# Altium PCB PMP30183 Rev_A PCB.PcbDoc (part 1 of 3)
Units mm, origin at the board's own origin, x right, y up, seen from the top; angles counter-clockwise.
Board outline 88.14 x 173.35 mm, 4 copper layers (Top Layer, Signal Layer 1, Signal Layer 2, Bottom Layer), stack 2.028 mm thick; 250 components, 133 nets, 589 pads, 226 vias.
Unrouted connection lines stored in the file: 1.
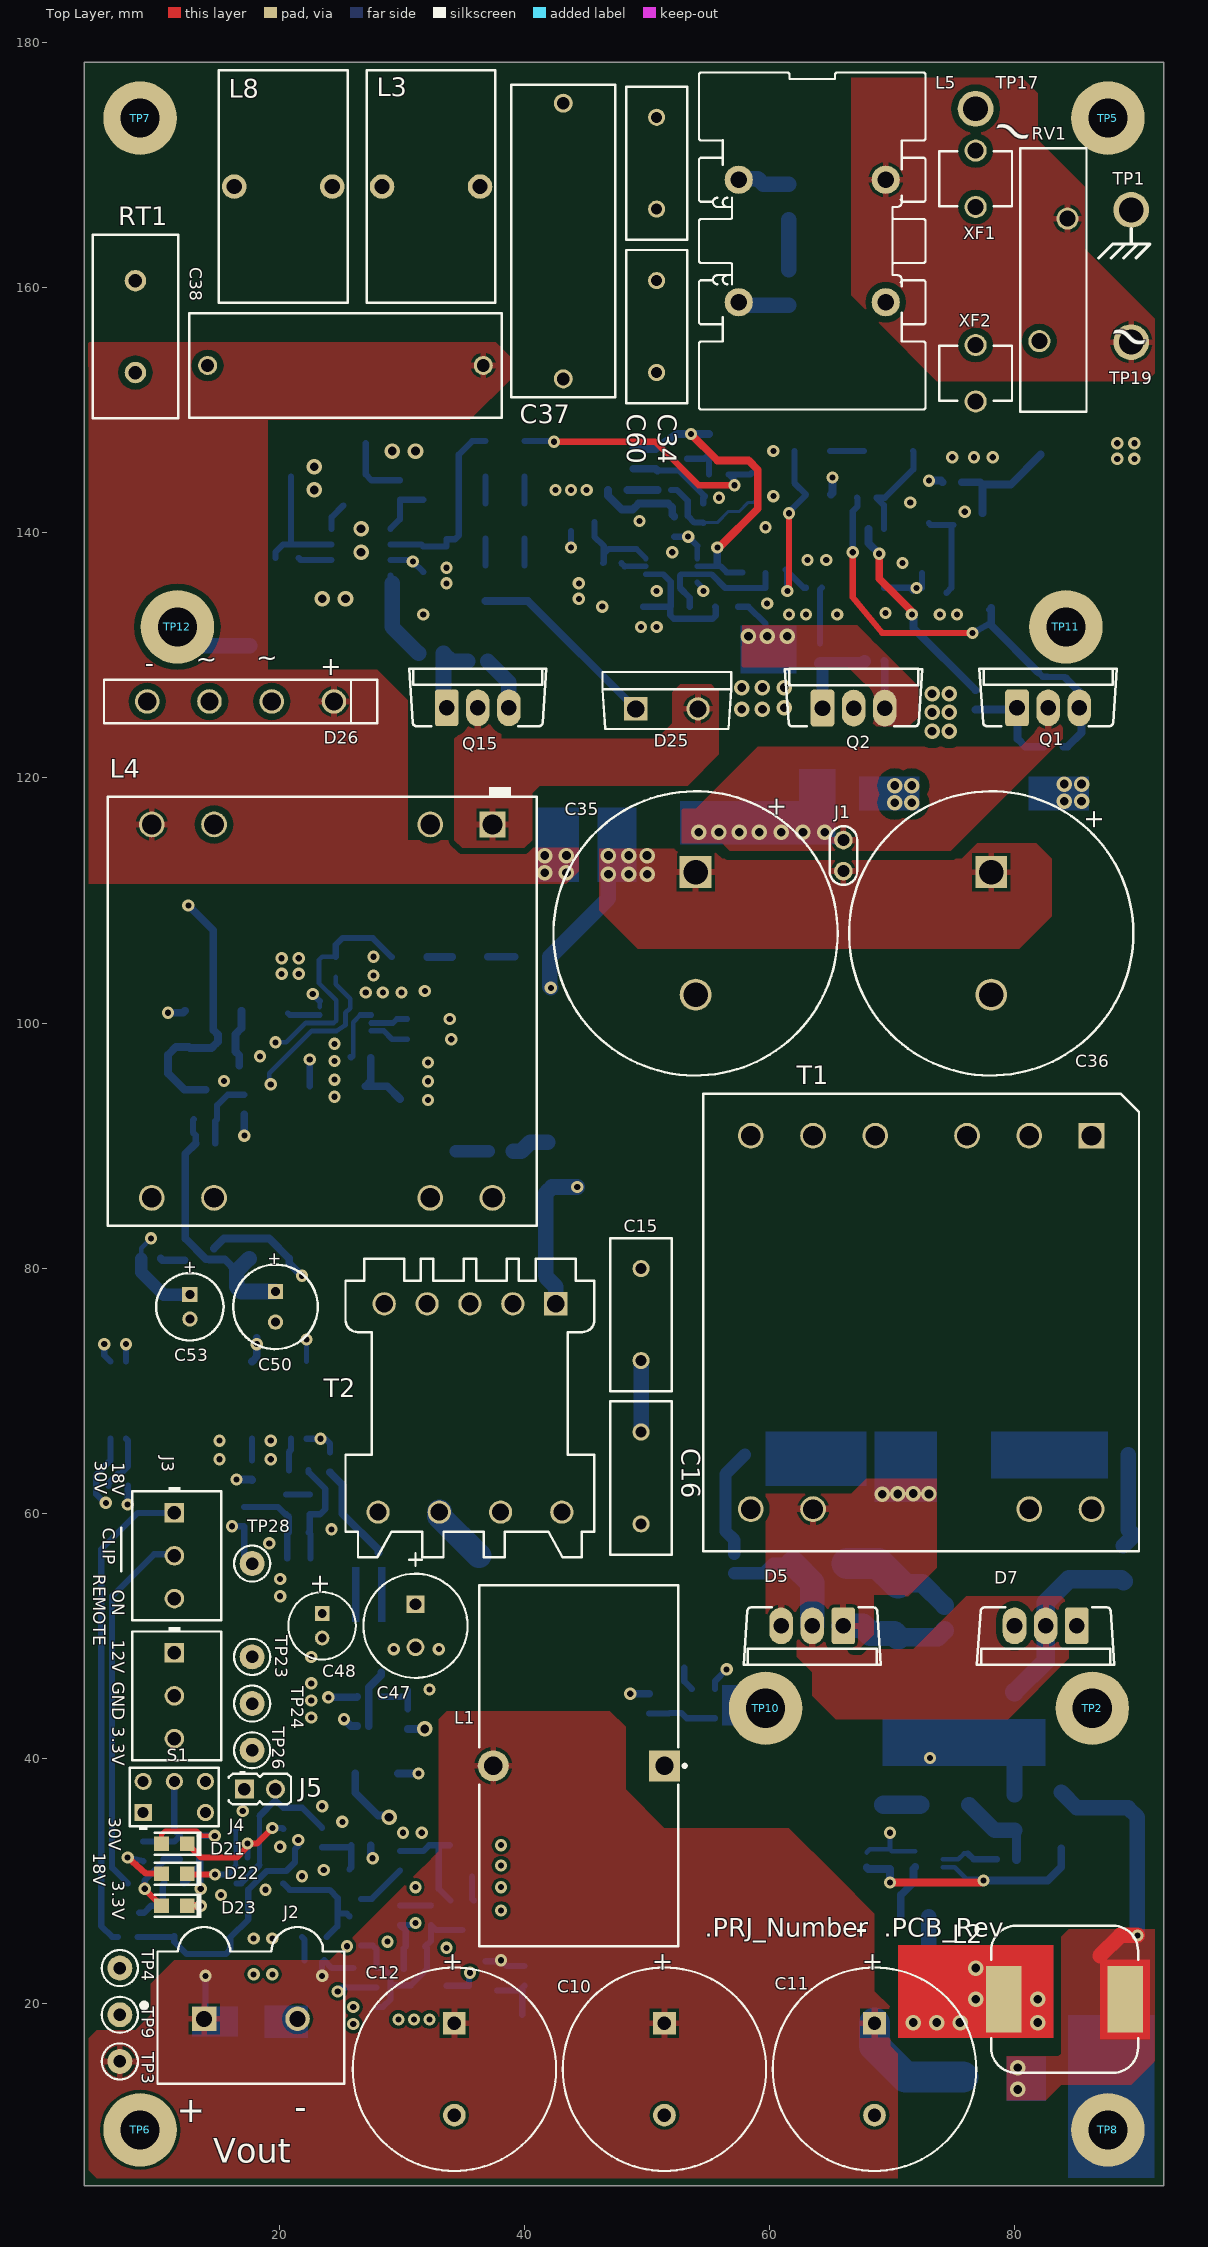
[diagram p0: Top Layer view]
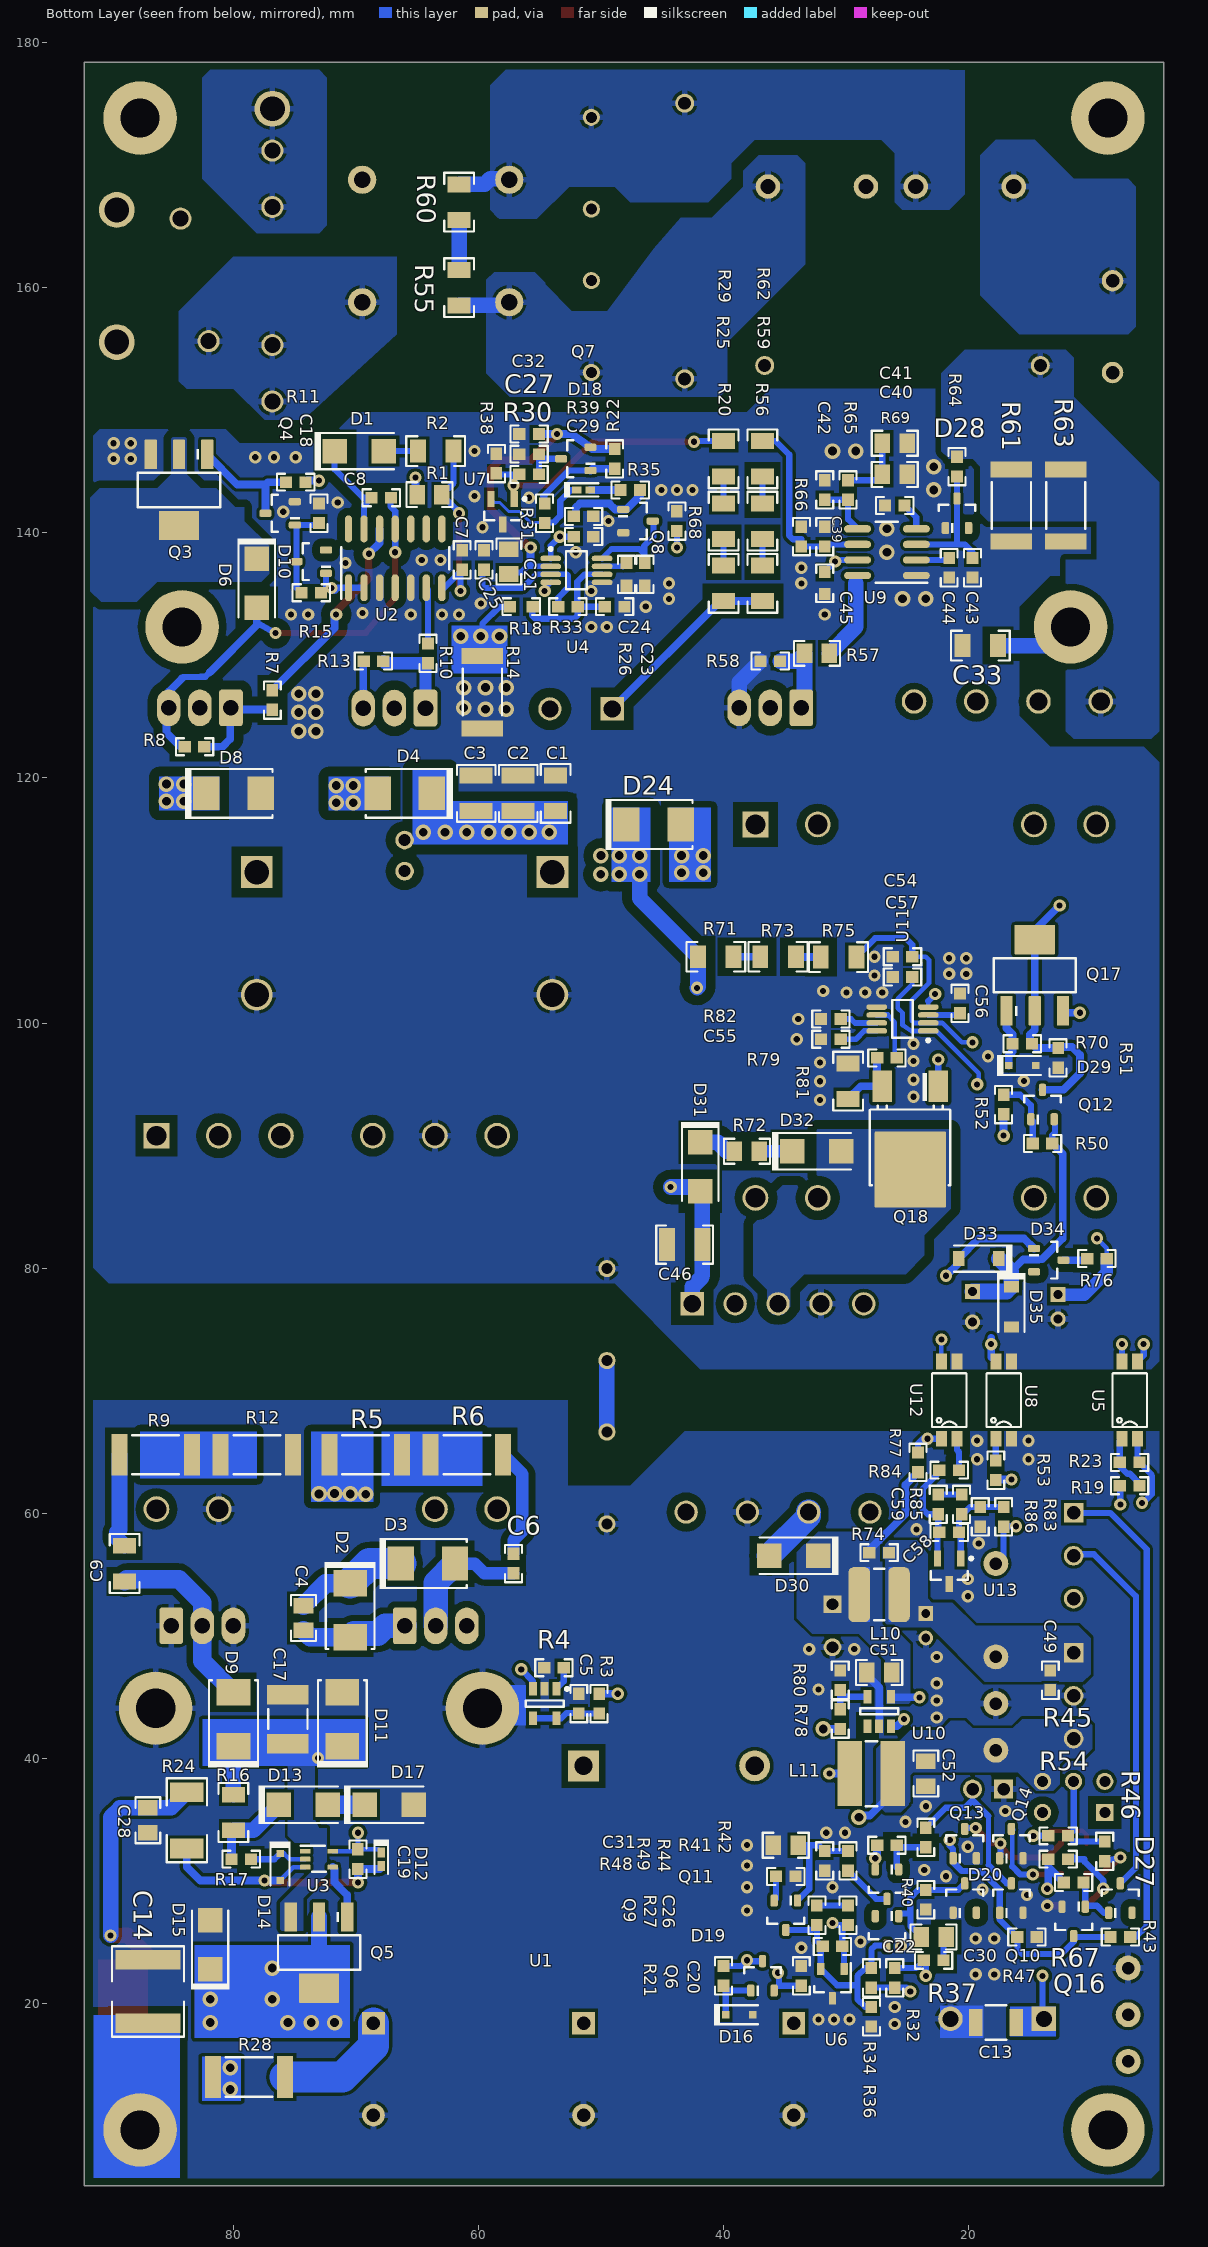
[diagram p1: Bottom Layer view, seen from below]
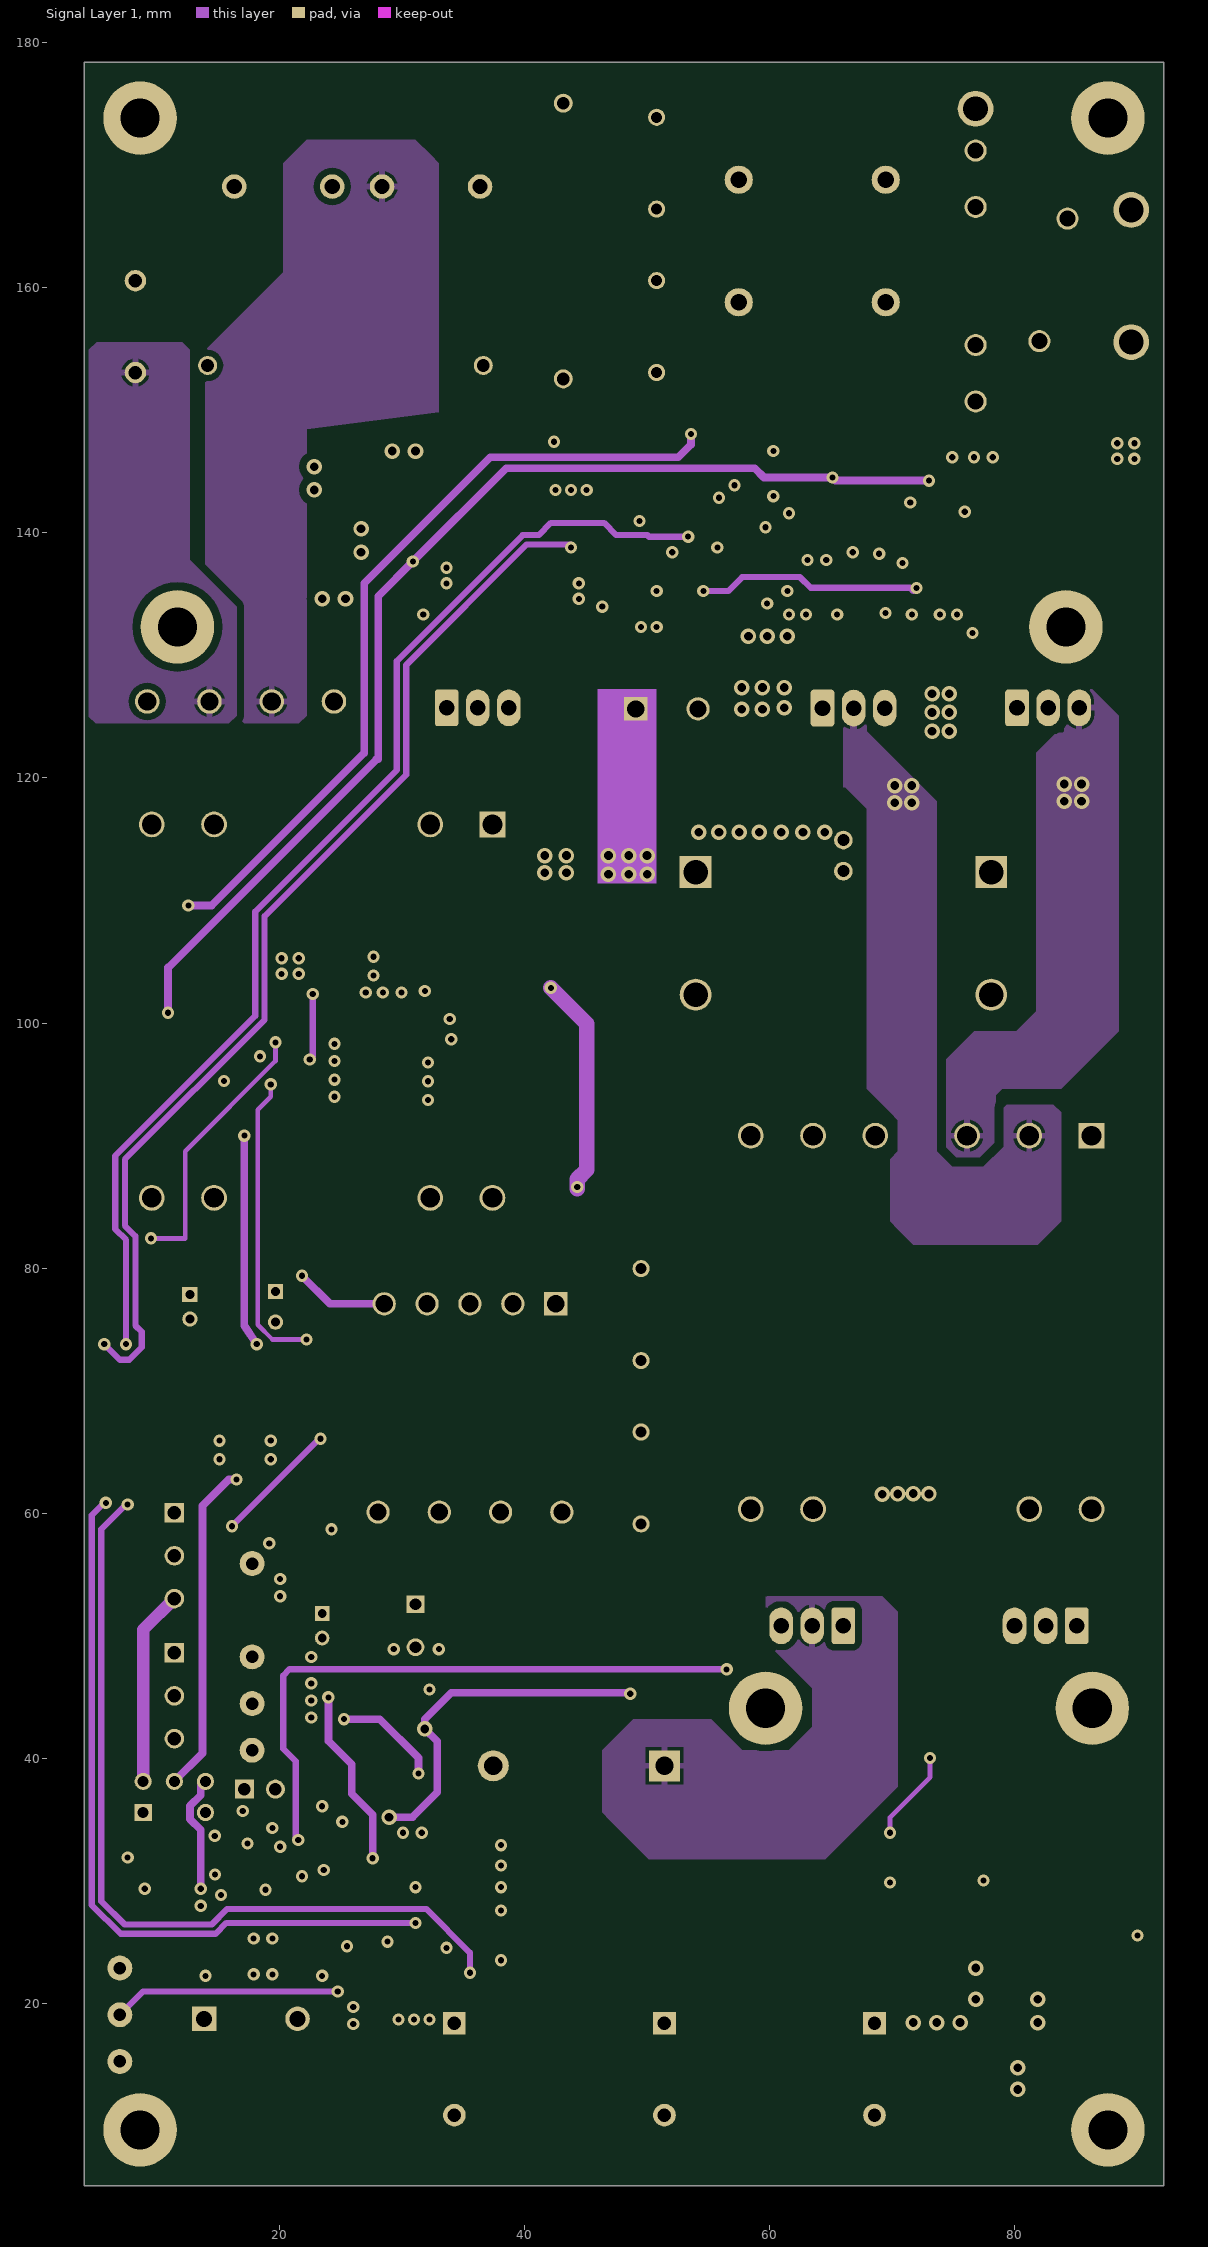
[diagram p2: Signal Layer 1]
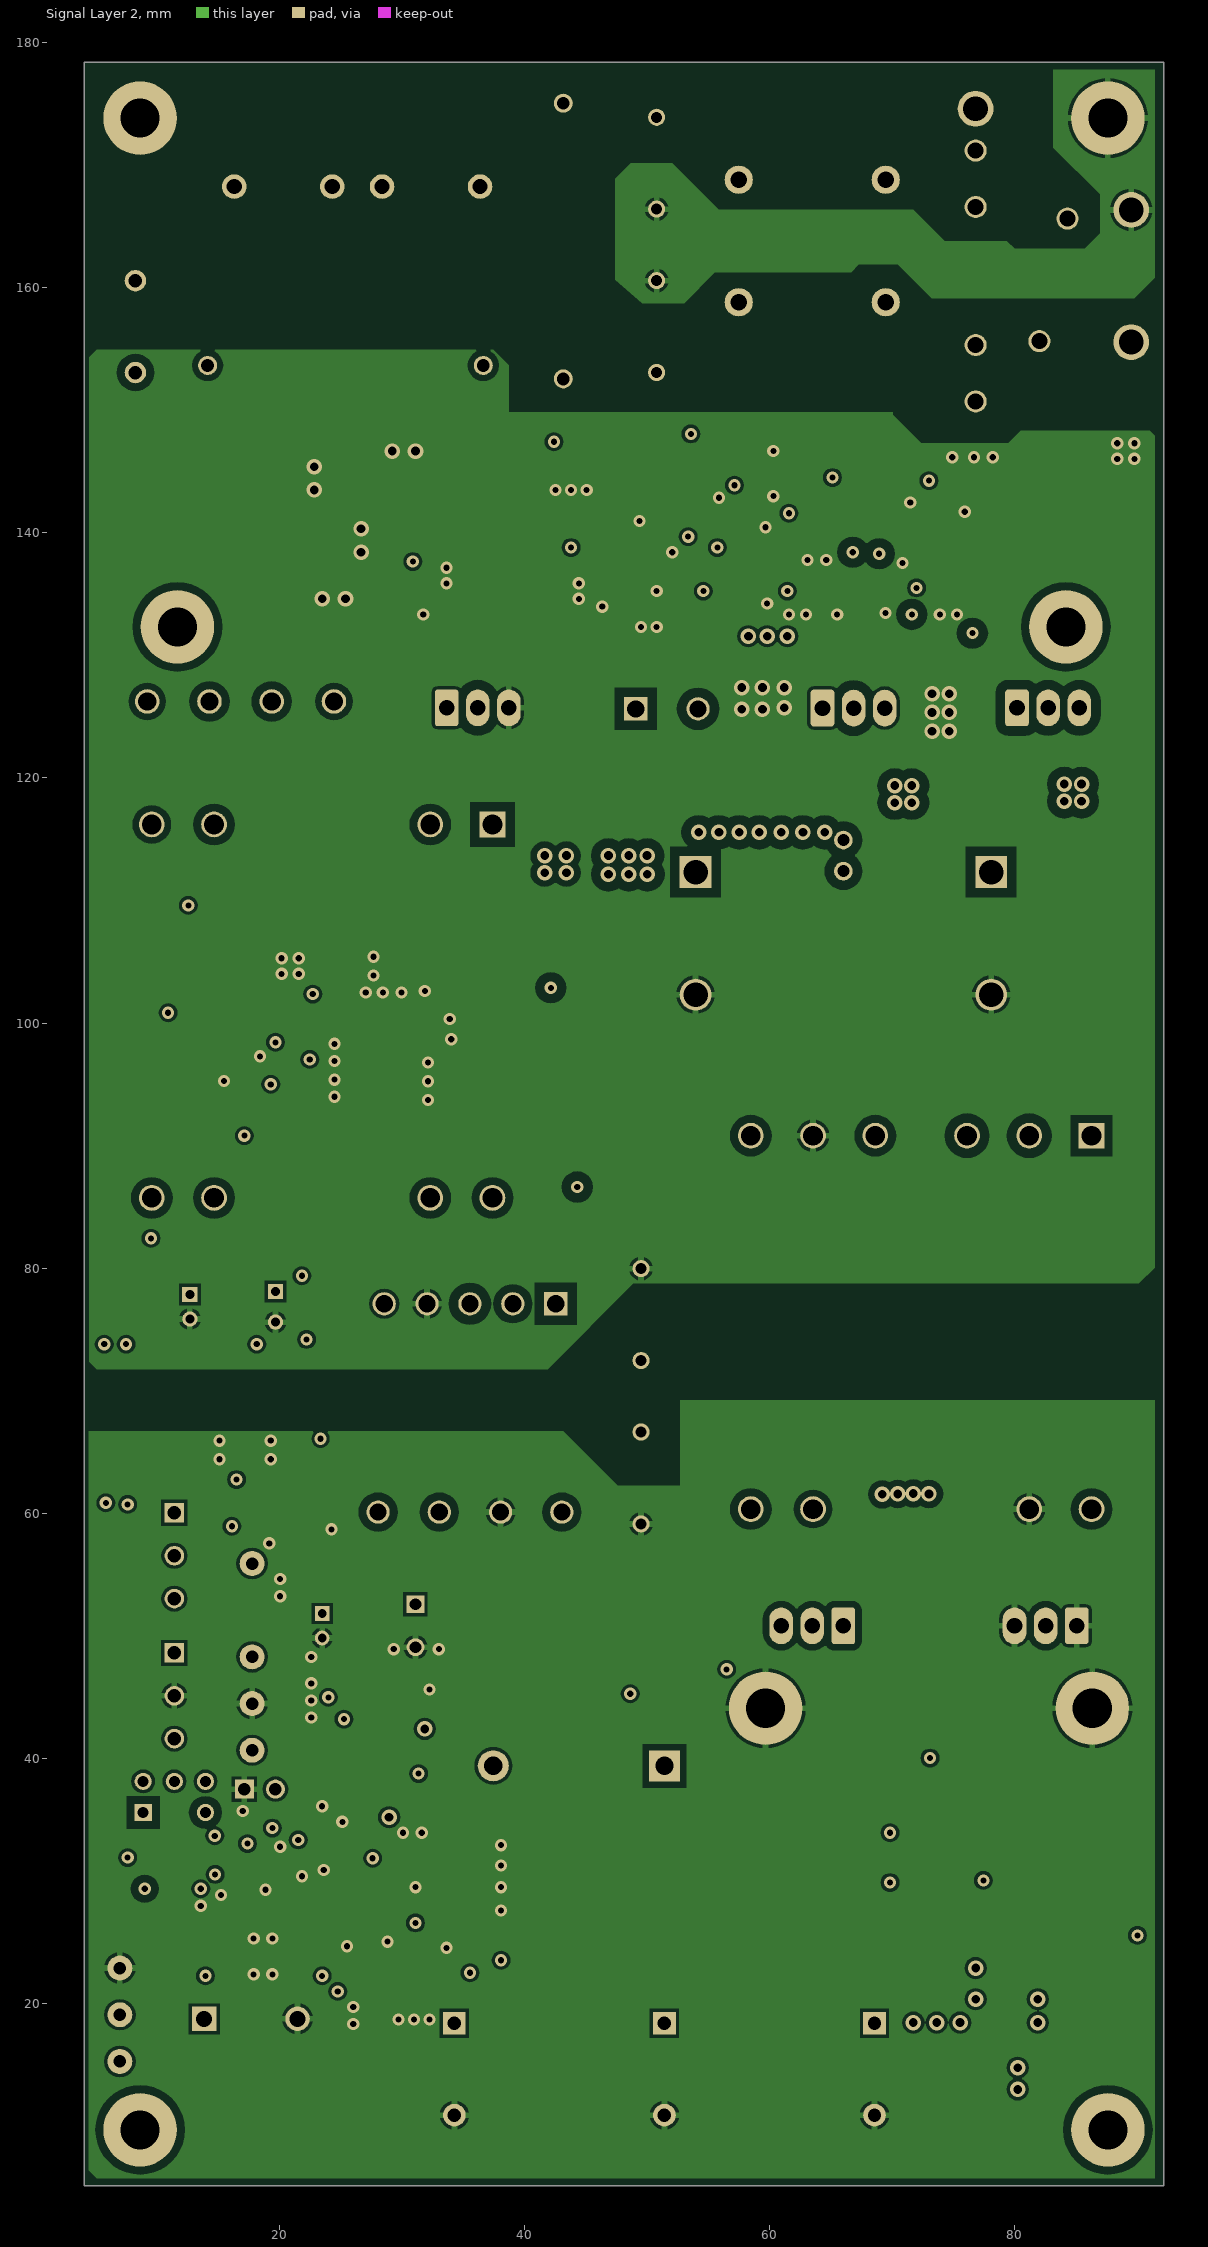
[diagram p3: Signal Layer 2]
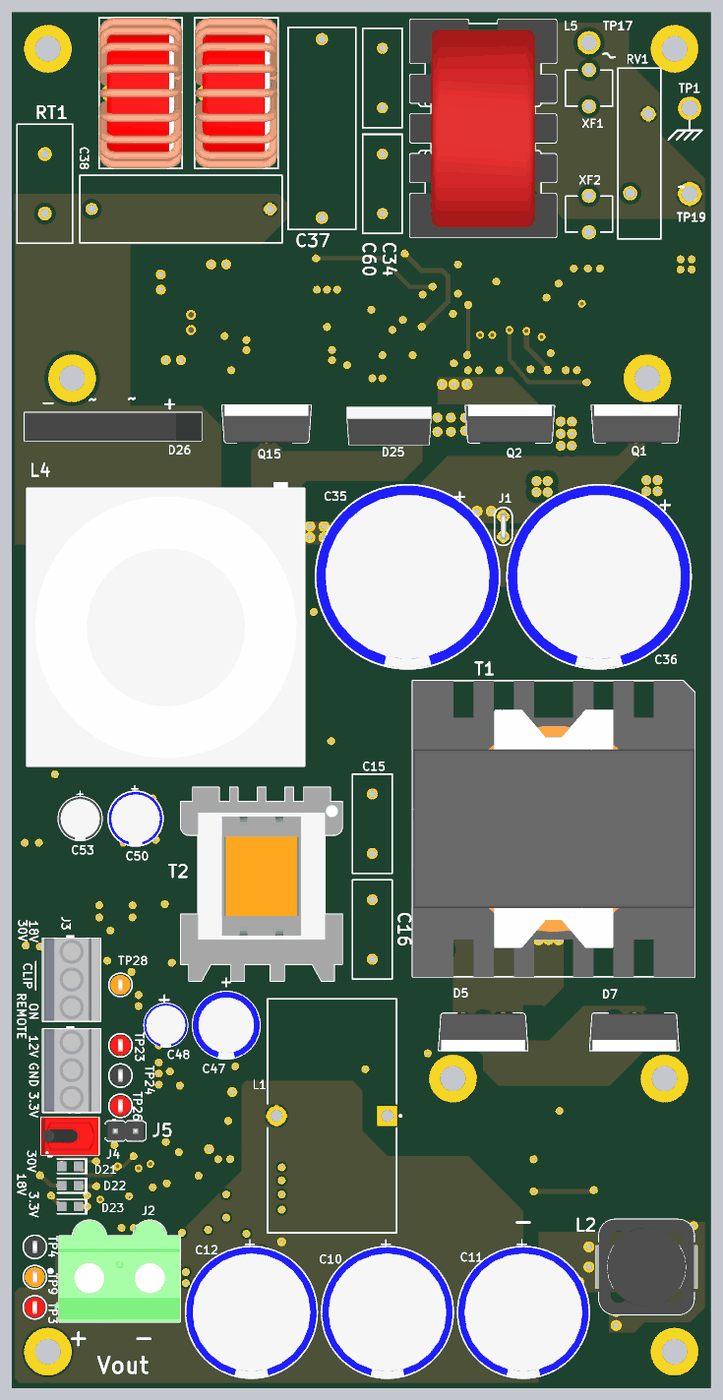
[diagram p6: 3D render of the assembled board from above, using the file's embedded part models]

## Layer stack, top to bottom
Top Solder: solder mask 0.0102, Solder Resist, Dk 3.5
Top Layer: signal copper 0.0356
Dielectric1: core 1.5037, FR-4, Dk 4.8
Signal Layer 1: signal copper 0.036
Dielectric 3: prepreg 0.127, Dk 4.2
Signal Layer 2: signal copper 0.036
Dielectric 2: core 0.254, Dk 4.2
Bottom Layer: signal copper 0.0356
Bottom Solder: solder mask 0.0102, Solder Resist, Dk 3.5

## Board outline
4.064,5.08 92.202,5.08 92.202,178.435 4.064,178.435

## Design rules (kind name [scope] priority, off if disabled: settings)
AcuteAngle [All] p1: minimum=4.50000000000000E+0001 checktracksonly=FALSE
AssemblyTestPointUsage [All] p1: valid=2
Clearance "Schematic Clearance Constraint_120" [InNet('NetR68_2')] p1: gap=0.254 ignorepadtopadclearanceinfootprint=FALSE except(0: Arc-Hole Track-Hole SMDPad-Hole THPad-Hole Via-Hole Fill-Hole Poly-Hole Region-Hole Text-Hole)
Clearance "Schematic Clearance Constraint_119" [InNet('NetC18_1')] p2: gap=0.254 ignorepadtopadclearanceinfootprint=FALSE except(0: Arc-Hole Track-Hole SMDPad-Hole THPad-Hole Via-Hole Fill-Hole Poly-Hole Region-Hole Text-Hole)
Clearance "Schematic Clearance Constraint_118" [InNet('NetC31_1')] p3: gap=0.254 ignorepadtopadclearanceinfootprint=FALSE except(0: Arc-Hole Track-Hole SMDPad-Hole THPad-Hole Via-Hole Fill-Hole Poly-Hole Region-Hole Text-Hole)
Clearance "Schematic Clearance Constraint_117" [InNet('NetD21_1')] p4: gap=0.254 ignorepadtopadclearanceinfootprint=FALSE except(0: Arc-Hole Track-Hole SMDPad-Hole THPad-Hole Via-Hole Fill-Hole Poly-Hole Region-Hole Text-Hole)
Clearance "Schematic Clearance Constraint_116" [InNet('NetD21_2')] p5: gap=0.254 ignorepadtopadclearanceinfootprint=FALSE except(0: Arc-Hole Track-Hole SMDPad-Hole THPad-Hole Via-Hole Fill-Hole Poly-Hole Region-Hole Text-Hole)
Clearance "Schematic Clearance Constraint_115" [InNet('NetD22_1')] p6: gap=0.254 ignorepadtopadclearanceinfootprint=FALSE except(0: Arc-Hole Track-Hole SMDPad-Hole THPad-Hole Via-Hole Fill-Hole Poly-Hole Region-Hole Text-Hole)
Clearance "Schematic Clearance Constraint_114" [InNet('NetD22_2')] p7: gap=0.254 ignorepadtopadclearanceinfootprint=FALSE except(0: Arc-Hole Track-Hole SMDPad-Hole THPad-Hole Via-Hole Fill-Hole Poly-Hole Region-Hole Text-Hole)
Clearance "Schematic Clearance Constraint_113" [InNet('NetD27_1')] p8: gap=0.254 ignorepadtopadclearanceinfootprint=FALSE except(0: Arc-Hole Track-Hole SMDPad-Hole THPad-Hole Via-Hole Fill-Hole Poly-Hole Region-Hole Text-Hole)
Clearance "Schematic Clearance Constraint_112" [InNet('NetD27_3')] p9: gap=0.254 ignorepadtopadclearanceinfootprint=FALSE except(0: Arc-Hole Track-Hole SMDPad-Hole THPad-Hole Via-Hole Fill-Hole Poly-Hole Region-Hole Text-Hole)
Clearance "Schematic Clearance Constraint_111" [InNet('NetJ5_2')] p10: gap=0.254 ignorepadtopadclearanceinfootprint=FALSE except(0: Arc-Hole Track-Hole SMDPad-Hole THPad-Hole Via-Hole Fill-Hole Poly-Hole Region-Hole Text-Hole)
Clearance "Schematic Clearance Constraint_108" [InNet('NetQ3_1')] p11: gap=0.254 ignorepadtopadclearanceinfootprint=FALSE except(0: Arc-Hole Track-Hole SMDPad-Hole THPad-Hole Via-Hole Fill-Hole Poly-Hole Region-Hole Text-Hole)
Clearance "Schematic Clearance Constraint_107" [InNet('NetQ9_2')] p12: gap=0.254 ignorepadtopadclearanceinfootprint=FALSE except(0: Arc-Hole Track-Hole SMDPad-Hole THPad-Hole Via-Hole Fill-Hole Poly-Hole Region-Hole Text-Hole)
Clearance "Schematic Clearance Constraint_106" [InNet('NetQ11_3')] p13: gap=0.254 ignorepadtopadclearanceinfootprint=FALSE except(0: Arc-Hole Track-Hole SMDPad-Hole THPad-Hole Via-Hole Fill-Hole Poly-Hole Region-Hole Text-Hole)
Clearance "Schematic Clearance Constraint_105" [InNet('NetC17_1')] p14: gap=0.254 ignorepadtopadclearanceinfootprint=FALSE except(0: Arc-Hole Track-Hole SMDPad-Hole THPad-Hole Via-Hole Fill-Hole Poly-Hole Region-Hole Text-Hole)
Clearance "Schematic Clearance Constraint_104" [InNet('NetC19_2')] p15: gap=0.254 ignorepadtopadclearanceinfootprint=FALSE except(0: Arc-Hole Track-Hole SMDPad-Hole THPad-Hole Via-Hole Fill-Hole Poly-Hole Region-Hole Text-Hole)
Clearance "Schematic Clearance Constraint_87" [InNet('NetC28_1')] p16: gap=0.254 ignorepadtopadclearanceinfootprint=FALSE except(0: Arc-Hole Track-Hole SMDPad-Hole THPad-Hole Via-Hole Fill-Hole Poly-Hole Region-Hole Text-Hole)
Clearance "Schematic Clearance Constraint_83" [InNet('NetD13_1')] p17: gap=0.254 ignorepadtopadclearanceinfootprint=FALSE except(0: Arc-Hole Track-Hole SMDPad-Hole THPad-Hole Via-Hole Fill-Hole Poly-Hole Region-Hole Text-Hole)
Clearance "Schematic Clearance Constraint_45" [InNet('NetD15_1')] p18: gap=0.254 ignorepadtopadclearanceinfootprint=FALSE except(0: Arc-Hole Track-Hole SMDPad-Hole THPad-Hole Via-Hole Fill-Hole Poly-Hole Region-Hole Text-Hole)
Clearance "Schematic Clearance Constraint_27" [InNet('NetQ5_1')] p19: gap=0.254 ignorepadtopadclearanceinfootprint=FALSE except(0: Arc-Hole Track-Hole SMDPad-Hole THPad-Hole Via-Hole Fill-Hole Poly-Hole Region-Hole Text-Hole)
Clearance "Schematic Clearance Constraint_82" [InNet('NetD13_2')] p20: gap=0.254 ignorepadtopadclearanceinfootprint=FALSE except(0: Arc-Hole Track-Hole SMDPad-Hole THPad-Hole Via-Hole Fill-Hole Poly-Hole Region-Hole Text-Hole)
Clearance "Schematic Clearance Constraint_80" [InNet('NetL5_2')] p21: gap=0.508 ignorepadtopadclearanceinfootprint=FALSE except(0: Arc-Hole Track-Hole SMDPad-Hole THPad-Hole Via-Hole Fill-Hole Poly-Hole Region-Hole Text-Hole)
Clearance "Schematic Clearance Constraint_76" [InNet('NetF1_2')] p22: gap=0.508 ignorepadtopadclearanceinfootprint=FALSE except(0: Arc-Hole Track-Hole SMDPad-Hole THPad-Hole Via-Hole Fill-Hole Poly-Hole Region-Hole Text-Hole)
Clearance "Schematic Clearance Constraint_57" [InNet('NetC6_2')] p23: gap=0.508 ignorepadtopadclearanceinfootprint=FALSE except(0: Arc-Hole Track-Hole SMDPad-Hole THPad-Hole Via-Hole Fill-Hole Poly-Hole Region-Hole Text-Hole)
Clearance "Schematic Clearance Constraint_110" [InNet('NetC4_1')] p24: gap=0.508 ignorepadtopadclearanceinfootprint=FALSE except(0: Arc-Hole Track-Hole SMDPad-Hole THPad-Hole Via-Hole Fill-Hole Poly-Hole Region-Hole Text-Hole)
Clearance "Schematic Clearance Constraint_109" [InNet('NetC9_2')] p25: gap=0.508 ignorepadtopadclearanceinfootprint=FALSE except(0: Arc-Hole Track-Hole SMDPad-Hole THPad-Hole Via-Hole Fill-Hole Poly-Hole Region-Hole Text-Hole)
Clearance "Schematic Clearance Constraint_103" [InNet('NetR5_2')] p26: gap=0.508 ignorepadtopadclearanceinfootprint=FALSE except(0: Arc-Hole Track-Hole SMDPad-Hole THPad-Hole Via-Hole Fill-Hole Poly-Hole Region-Hole Text-Hole)
Clearance "Schematic Clearance Constraint_102" [InNet('NetR9_1')] p27: gap=0.508 ignorepadtopadclearanceinfootprint=FALSE except(0: Arc-Hole Track-Hole SMDPad-Hole THPad-Hole Via-Hole Fill-Hole Poly-Hole Region-Hole Text-Hole)
Clearance "Schematic Clearance Constraint_101" [InNet('OVER_TEMPERATURE')] p28: gap=0.254 ignorepadtopadclearanceinfootprint=FALSE except(0: Arc-Hole Track-Hole SMDPad-Hole THPad-Hole Via-Hole Fill-Hole Poly-Hole Region-Hole Text-Hole)
Clearance "Schematic Clearance Constraint_93" [InNet('NetC5_1')] p29: gap=0.254 ignorepadtopadclearanceinfootprint=FALSE except(0: Arc-Hole Track-Hole SMDPad-Hole THPad-Hole Via-Hole Fill-Hole Poly-Hole Region-Hole Text-Hole)
Clearance "Schematic Clearance Constraint_77" [InNet('NetR4_1')] p30: gap=0.254 ignorepadtopadclearanceinfootprint=FALSE except(0: Arc-Hole Track-Hole SMDPad-Hole THPad-Hole Via-Hole Fill-Hole Poly-Hole Region-Hole Text-Hole)
Clearance "Schematic Clearance Constraint_37" [InNet('NetJ3_1')] p31: gap=0.254 ignorepadtopadclearanceinfootprint=FALSE except(0: Arc-Hole Track-Hole SMDPad-Hole THPad-Hole Via-Hole Fill-Hole Poly-Hole Region-Hole Text-Hole)
Clearance "Schematic Clearance Constraint_24" [InNet('VOUT')] p32: gap=0.254 ignorepadtopadclearanceinfootprint=FALSE except(0: Arc-Hole Track-Hole SMDPad-Hole THPad-Hole Via-Hole Fill-Hole Poly-Hole Region-Hole Text-Hole)
Clearance "Schematic Clearance Constraint_12" [InNet('NetD18_1')] p33: gap=0.254 ignorepadtopadclearanceinfootprint=FALSE except(0: Arc-Hole Track-Hole SMDPad-Hole THPad-Hole Via-Hole Fill-Hole Poly-Hole Region-Hole Text-Hole)
Clearance "Schematic Clearance Constraint_100" [InNet('NetD31_1')] p34: gap=0.762 ignorepadtopadclearanceinfootprint=FALSE except(0: Arc-Hole Track-Hole SMDPad-Hole THPad-Hole Via-Hole Fill-Hole Poly-Hole Region-Hole Text-Hole)
Clearance "Schematic Clearance Constraint_99" [InNet('NetD32_1')] p35: gap=0.762 ignorepadtopadclearanceinfootprint=FALSE except(0: Arc-Hole Track-Hole SMDPad-Hole THPad-Hole Via-Hole Fill-Hole Poly-Hole Region-Hole Text-Hole)
Clearance "Schematic Clearance Constraint_98" [InNet('NetD32_2')] p36: gap=0.762 ignorepadtopadclearanceinfootprint=FALSE except(0: Arc-Hole Track-Hole SMDPad-Hole THPad-Hole Via-Hole Fill-Hole Poly-Hole Region-Hole Text-Hole)
Clearance "Schematic Clearance Constraint_97" [InNet('NetC1_1')] p37: gap=0.762 ignorepadtopadclearanceinfootprint=FALSE except(0: Arc-Hole Track-Hole SMDPad-Hole THPad-Hole Via-Hole Fill-Hole Poly-Hole Region-Hole Text-Hole)
Clearance "Schematic Clearance Constraint_96" [InNet('NetC8_1')] p38: gap=0.762 ignorepadtopadclearanceinfootprint=FALSE except(0: Arc-Hole Track-Hole SMDPad-Hole THPad-Hole Via-Hole Fill-Hole Poly-Hole Region-Hole Text-Hole)
Clearance "Schematic Clearance Constraint_95" [InNet('NetC8_2')] p39: gap=0.762 ignorepadtopadclearanceinfootprint=FALSE except(0: Arc-Hole Track-Hole SMDPad-Hole THPad-Hole Via-Hole Fill-Hole Poly-Hole Region-Hole Text-Hole)
Clearance "Schematic Clearance Constraint_94" [InNet('NetD4_2')] p40: gap=0.762 ignorepadtopadclearanceinfootprint=FALSE except(0: Arc-Hole Track-Hole SMDPad-Hole THPad-Hole Via-Hole Fill-Hole Poly-Hole Region-Hole Text-Hole)
Clearance "Schematic Clearance Constraint_92" [InNet('NetQ1_1')] p41: gap=0.762 ignorepadtopadclearanceinfootprint=FALSE except(0: Arc-Hole Track-Hole SMDPad-Hole THPad-Hole Via-Hole Fill-Hole Poly-Hole Region-Hole Text-Hole)
Clearance "Schematic Clearance Constraint_91" [InNet('NetR7_1')] p42: gap=0.762 ignorepadtopadclearanceinfootprint=FALSE except(0: Arc-Hole Track-Hole SMDPad-Hole THPad-Hole Via-Hole Fill-Hole Poly-Hole Region-Hole Text-Hole)
Clearance "Schematic Clearance Constraint_90" [InNet('+400V')] p43: gap=0.762 ignorepadtopadclearanceinfootprint=FALSE except(0: Arc-Hole Track-Hole SMDPad-Hole THPad-Hole Via-Hole Fill-Hole Poly-Hole Region-Hole Text-Hole)
Clearance "Schematic Clearance Constraint_89" [InNet('NetC34_2')] p44: gap=0.508 ignorepadtopadclearanceinfootprint=FALSE except(0: Arc-Hole Track-Hole SMDPad-Hole THPad-Hole Via-Hole Fill-Hole Poly-Hole Region-Hole Text-Hole)
Clearance "Schematic Clearance Constraint_88" [InNet('NetC37_2')] p45: gap=0.508 ignorepadtopadclearanceinfootprint=FALSE except(0: Arc-Hole Track-Hole SMDPad-Hole THPad-Hole Via-Hole Fill-Hole Poly-Hole Region-Hole Text-Hole)
Clearance "Schematic Clearance Constraint_86" [InNet('NetC38_1')] p46: gap=0.508 ignorepadtopadclearanceinfootprint=FALSE except(0: Arc-Hole Track-Hole SMDPad-Hole THPad-Hole Via-Hole Fill-Hole Poly-Hole Region-Hole Text-Hole)
Clearance "Schematic Clearance Constraint_85" [InNet('NetC38_2')] p47: gap=0.508 ignorepadtopadclearanceinfootprint=FALSE except(0: Arc-Hole Track-Hole SMDPad-Hole THPad-Hole Via-Hole Fill-Hole Poly-Hole Region-Hole Text-Hole)
Clearance "Schematic Clearance Constraint_84" [InNet('NetF1_1')] p48: gap=0.508 ignorepadtopadclearanceinfootprint=FALSE except(0: Arc-Hole Track-Hole SMDPad-Hole THPad-Hole Via-Hole Fill-Hole Poly-Hole Region-Hole Text-Hole)
Clearance "Schematic Clearance Constraint_81" [InNet('NetR59_1')] p49: gap=0.508 ignorepadtopadclearanceinfootprint=FALSE except(0: Arc-Hole Track-Hole SMDPad-Hole THPad-Hole Via-Hole Fill-Hole Poly-Hole Region-Hole Text-Hole)
Clearance "Schematic Clearance Constraint_79" [InNet('NetC4_2')] p50: gap=0.508 ignorepadtopadclearanceinfootprint=FALSE except(0: Arc-Hole Track-Hole SMDPad-Hole THPad-Hole Via-Hole Fill-Hole Poly-Hole Region-Hole Text-Hole)
Clearance "Schematic Clearance Constraint_78" [InNet('NetC6_1')] p51: gap=0.508 ignorepadtopadclearanceinfootprint=FALSE except(0: Arc-Hole Track-Hole SMDPad-Hole THPad-Hole Via-Hole Fill-Hole Poly-Hole Region-Hole Text-Hole)
Clearance "Schematic Clearance Constraint_75" [InNet('NetR20_1')] p52: gap=0.508 ignorepadtopadclearanceinfootprint=FALSE except(0: Arc-Hole Track-Hole SMDPad-Hole THPad-Hole Via-Hole Fill-Hole Poly-Hole Region-Hole Text-Hole)
Clearance "Schematic Clearance Constraint_73" [InNet('NetC38_2')] p53: gap=0.254 ignorepadtopadclearanceinfootprint=FALSE except(0: Arc-Hole Track-Hole SMDPad-Hole THPad-Hole Via-Hole Fill-Hole Poly-Hole Region-Hole Text-Hole)
Clearance "Schematic Clearance Constraint_72" [InNet('NetC39_1')] p54: gap=0.254 ignorepadtopadclearanceinfootprint=FALSE except(0: Arc-Hole Track-Hole SMDPad-Hole THPad-Hole Via-Hole Fill-Hole Poly-Hole Region-Hole Text-Hole)
Clearance "Schematic Clearance Constraint_71" [InNet('NetC40_1')] p55: gap=0.254 ignorepadtopadclearanceinfootprint=FALSE except(0: Arc-Hole Track-Hole SMDPad-Hole THPad-Hole Via-Hole Fill-Hole Poly-Hole Region-Hole Text-Hole)
Clearance "Schematic Clearance Constraint_70" [InNet('NetC42_1')] p56: gap=0.254 ignorepadtopadclearanceinfootprint=FALSE except(0: Arc-Hole Track-Hole SMDPad-Hole THPad-Hole Via-Hole Fill-Hole Poly-Hole Region-Hole Text-Hole)
Clearance "Schematic Clearance Constraint_69" [InNet('NetC43_1')] p57: gap=0.254 ignorepadtopadclearanceinfootprint=FALSE except(0: Arc-Hole Track-Hole SMDPad-Hole THPad-Hole Via-Hole Fill-Hole Poly-Hole Region-Hole Text-Hole)
Clearance "Schematic Clearance Constraint_68" [InNet('NetC44_1')] p58: gap=0.254 ignorepadtopadclearanceinfootprint=FALSE except(0: Arc-Hole Track-Hole SMDPad-Hole THPad-Hole Via-Hole Fill-Hole Poly-Hole Region-Hole Text-Hole)
Clearance "Schematic Clearance Constraint_67" [InNet('NetC48_1')] p59: gap=0.254 ignorepadtopadclearanceinfootprint=FALSE except(0: Arc-Hole Track-Hole SMDPad-Hole THPad-Hole Via-Hole Fill-Hole Poly-Hole Region-Hole Text-Hole)
Clearance "Schematic Clearance Constraint_66" [InNet('NetC53_1')] p60: gap=0.254 ignorepadtopadclearanceinfootprint=FALSE except(0: Arc-Hole Track-Hole SMDPad-Hole THPad-Hole Via-Hole Fill-Hole Poly-Hole Region-Hole Text-Hole)
Clearance "Schematic Clearance Constraint_65" [InNet('NetC55_1')] p61: gap=0.254 ignorepadtopadclearanceinfootprint=FALSE except(0: Arc-Hole Track-Hole SMDPad-Hole THPad-Hole Via-Hole Fill-Hole Poly-Hole Region-Hole Text-Hole)
Clearance "Schematic Clearance Constraint_64" [InNet('NetC56_1')] p62: gap=0.254 ignorepadtopadclearanceinfootprint=FALSE except(0: Arc-Hole Track-Hole SMDPad-Hole THPad-Hole Via-Hole Fill-Hole Poly-Hole Region-Hole Text-Hole)
Clearance "Schematic Clearance Constraint_63" [InNet('NetC57_1')] p63: gap=0.254 ignorepadtopadclearanceinfootprint=FALSE except(0: Arc-Hole Track-Hole SMDPad-Hole THPad-Hole Via-Hole Fill-Hole Poly-Hole Region-Hole Text-Hole)
Clearance "Schematic Clearance Constraint_62" [InNet('NetC58_1')] p64: gap=0.254 ignorepadtopadclearanceinfootprint=FALSE except(0: Arc-Hole Track-Hole SMDPad-Hole THPad-Hole Via-Hole Fill-Hole Poly-Hole Region-Hole Text-Hole)
Clearance "Schematic Clearance Constraint_61" [InNet('NetC58_2')] p65: gap=0.254 ignorepadtopadclearanceinfootprint=FALSE except(0: Arc-Hole Track-Hole SMDPad-Hole THPad-Hole Via-Hole Fill-Hole Poly-Hole Region-Hole Text-Hole)
Clearance "Schematic Clearance Constraint_60" [InNet('NetC59_1')] p66: gap=0.254 ignorepadtopadclearanceinfootprint=FALSE except(0: Arc-Hole Track-Hole SMDPad-Hole THPad-Hole Via-Hole Fill-Hole Poly-Hole Region-Hole Text-Hole)
Clearance "Schematic Clearance Constraint_59" [InNet('NetD29_1')] p67: gap=0.254 ignorepadtopadclearanceinfootprint=FALSE except(0: Arc-Hole Track-Hole SMDPad-Hole THPad-Hole Via-Hole Fill-Hole Poly-Hole Region-Hole Text-Hole)
Clearance "Schematic Clearance Constraint_58" [InNet('NetD33_2')] p68: gap=0.254 ignorepadtopadclearanceinfootprint=FALSE except(0: Arc-Hole Track-Hole SMDPad-Hole THPad-Hole Via-Hole Fill-Hole Poly-Hole Region-Hole Text-Hole)
Clearance "Schematic Clearance Constraint_56" [InNet('NetL11_1')] p69: gap=0.254 ignorepadtopadclearanceinfootprint=FALSE except(0: Arc-Hole Track-Hole SMDPad-Hole THPad-Hole Via-Hole Fill-Hole Poly-Hole Region-Hole Text-Hole)
Clearance "Schematic Clearance Constraint_55" [InNet('NetQ18_1')] p70: gap=0.254 ignorepadtopadclearanceinfootprint=FALSE except(0: Arc-Hole Track-Hole SMDPad-Hole THPad-Hole Via-Hole Fill-Hole Poly-Hole Region-Hole Text-Hole)
Clearance "Schematic Clearance Constraint_54" [InNet('NetQ18_3')] p71: gap=0.254 ignorepadtopadclearanceinfootprint=FALSE except(0: Arc-Hole Track-Hole SMDPad-Hole THPad-Hole Via-Hole Fill-Hole Poly-Hole Region-Hole Text-Hole)
Clearance "Schematic Clearance Constraint_53" [InNet('NetR69_2')] p72: gap=0.254 ignorepadtopadclearanceinfootprint=FALSE except(0: Arc-Hole Track-Hole SMDPad-Hole THPad-Hole Via-Hole Fill-Hole Poly-Hole Region-Hole Text-Hole)
Clearance "Schematic Clearance Constraint_52" [InNet('NetR77_1')] p73: gap=0.254 ignorepadtopadclearanceinfootprint=FALSE except(0: Arc-Hole Track-Hole SMDPad-Hole THPad-Hole Via-Hole Fill-Hole Poly-Hole Region-Hole Text-Hole)
Clearance "Schematic Clearance Constraint_51" [InNet('NetR78_1')] p74: gap=0.254 ignorepadtopadclearanceinfootprint=FALSE except(0: Arc-Hole Track-Hole SMDPad-Hole THPad-Hole Via-Hole Fill-Hole Poly-Hole Region-Hole Text-Hole)
Clearance "Schematic Clearance Constraint_50" [InNet('NetR79_1')] p75: gap=0.254 ignorepadtopadclearanceinfootprint=FALSE except(0: Arc-Hole Track-Hole SMDPad-Hole THPad-Hole Via-Hole Fill-Hole Poly-Hole Region-Hole Text-Hole)
Clearance "Schematic Clearance Constraint_49" [InNet('NetR82_2')] p76: gap=0.254 ignorepadtopadclearanceinfootprint=FALSE except(0: Arc-Hole Track-Hole SMDPad-Hole THPad-Hole Via-Hole Fill-Hole Poly-Hole Region-Hole Text-Hole)
Clearance "Schematic Clearance Constraint_48" [InNet('+12VSEC')] p77: gap=0.254 ignorepadtopadclearanceinfootprint=FALSE except(0: Arc-Hole Track-Hole SMDPad-Hole THPad-Hole Via-Hole Fill-Hole Poly-Hole Region-Hole Text-Hole)
Clearance "Schematic Clearance Constraint_46" [InNet('NetC7_1')] p78: gap=0.254 ignorepadtopadclearanceinfootprint=FALSE except(0: Arc-Hole Track-Hole SMDPad-Hole THPad-Hole Via-Hole Fill-Hole Poly-Hole Region-Hole Text-Hole)
Clearance "Schematic Clearance Constraint_44" [InNet('NetR29_1')] p79: gap=0.254 ignorepadtopadclearanceinfootprint=FALSE except(0: Arc-Hole Track-Hole SMDPad-Hole THPad-Hole Via-Hole Fill-Hole Poly-Hole Region-Hole Text-Hole)
Clearance "Schematic Clearance Constraint_43" [InNet('NetC20_1')] p80: gap=0.254 ignorepadtopadclearanceinfootprint=FALSE except(0: Arc-Hole Track-Hole SMDPad-Hole THPad-Hole Via-Hole Fill-Hole Poly-Hole Region-Hole Text-Hole)
Clearance "Schematic Clearance Constraint_42" [InNet('NetC23_1')] p81: gap=0.254 ignorepadtopadclearanceinfootprint=FALSE except(0: Arc-Hole Track-Hole SMDPad-Hole THPad-Hole Via-Hole Fill-Hole Poly-Hole Region-Hole Text-Hole)
Clearance "Schematic Clearance Constraint_41" [InNet('NetC22_1')] p82: gap=0.254 ignorepadtopadclearanceinfootprint=FALSE except(0: Arc-Hole Track-Hole SMDPad-Hole THPad-Hole Via-Hole Fill-Hole Poly-Hole Region-Hole Text-Hole)
Clearance "Schematic Clearance Constraint_40" [InNet('NetC22_2')] p83: gap=0.254 ignorepadtopadclearanceinfootprint=FALSE except(0: Arc-Hole Track-Hole SMDPad-Hole THPad-Hole Via-Hole Fill-Hole Poly-Hole Region-Hole Text-Hole)
Clearance "Schematic Clearance Constraint_39" [InNet('NetC25_1')] p84: gap=0.254 ignorepadtopadclearanceinfootprint=FALSE except(0: Arc-Hole Track-Hole SMDPad-Hole THPad-Hole Via-Hole Fill-Hole Poly-Hole Region-Hole Text-Hole)
Clearance "Schematic Clearance Constraint_38" [InNet('NetC26_1')] p85: gap=0.254 ignorepadtopadclearanceinfootprint=FALSE except(0: Arc-Hole Track-Hole SMDPad-Hole THPad-Hole Via-Hole Fill-Hole Poly-Hole Region-Hole Text-Hole)
Clearance "Schematic Clearance Constraint_36" [InNet('NetC30_2')] p86: gap=0.254 ignorepadtopadclearanceinfootprint=FALSE except(0: Arc-Hole Track-Hole SMDPad-Hole THPad-Hole Via-Hole Fill-Hole Poly-Hole Region-Hole Text-Hole)
Clearance "Schematic Clearance Constraint_34" [InNet('NetD1_2')] p87: gap=0.254 ignorepadtopadclearanceinfootprint=FALSE except(0: Arc-Hole Track-Hole SMDPad-Hole THPad-Hole Via-Hole Fill-Hole Poly-Hole Region-Hole Text-Hole)
Clearance "Schematic Clearance Constraint_33" [InNet('NetD16_1')] p88: gap=0.254 ignorepadtopadclearanceinfootprint=FALSE except(0: Arc-Hole Track-Hole SMDPad-Hole THPad-Hole Via-Hole Fill-Hole Poly-Hole Region-Hole Text-Hole)
Clearance "Schematic Clearance Constraint_32" [InNet('NetC27_1')] p89: gap=0.254 ignorepadtopadclearanceinfootprint=FALSE except(0: Arc-Hole Track-Hole SMDPad-Hole THPad-Hole Via-Hole Fill-Hole Poly-Hole Region-Hole Text-Hole)
Clearance "Schematic Clearance Constraint_31" [InNet('NetD18_2')] p90: gap=0.254 ignorepadtopadclearanceinfootprint=FALSE except(0: Arc-Hole Track-Hole SMDPad-Hole THPad-Hole Via-Hole Fill-Hole Poly-Hole Region-Hole Text-Hole)
Clearance "Schematic Clearance Constraint_30" [InNet('NetJ3_3')] p91: gap=0.254 ignorepadtopadclearanceinfootprint=FALSE except(0: Arc-Hole Track-Hole SMDPad-Hole THPad-Hole Via-Hole Fill-Hole Poly-Hole Region-Hole Text-Hole)
Clearance "Schematic Clearance Constraint_29" [InNet('NetQ2_1')] p92: gap=0.254 ignorepadtopadclearanceinfootprint=FALSE except(0: Arc-Hole Track-Hole SMDPad-Hole THPad-Hole Via-Hole Fill-Hole Poly-Hole Region-Hole Text-Hole)
Clearance "Schematic Clearance Constraint_28" [InNet('NetQ2_3')] p93: gap=0.254 ignorepadtopadclearanceinfootprint=FALSE except(0: Arc-Hole Track-Hole SMDPad-Hole THPad-Hole Via-Hole Fill-Hole Poly-Hole Region-Hole Text-Hole)
Clearance "Schematic Clearance Constraint_26" [InNet('NetQ7_1')] p94: gap=0.254 ignorepadtopadclearanceinfootprint=FALSE except(0: Arc-Hole Track-Hole SMDPad-Hole THPad-Hole Via-Hole Fill-Hole Poly-Hole Region-Hole Text-Hole)
Clearance "Schematic Clearance Constraint_25" [InNet('NetQ8_1')] p95: gap=0.254 ignorepadtopadclearanceinfootprint=FALSE except(0: Arc-Hole Track-Hole SMDPad-Hole THPad-Hole Via-Hole Fill-Hole Poly-Hole Region-Hole Text-Hole)
Clearance "Schematic Clearance Constraint_23" [InNet('NetR10_1')] p96: gap=0.254 ignorepadtopadclearanceinfootprint=FALSE except(0: Arc-Hole Track-Hole SMDPad-Hole THPad-Hole Via-Hole Fill-Hole Poly-Hole Region-Hole Text-Hole)
Clearance "Schematic Clearance Constraint_22" [InNet('NetC24_1')] p97: gap=0.254 ignorepadtopadclearanceinfootprint=FALSE except(0: Arc-Hole Track-Hole SMDPad-Hole THPad-Hole Via-Hole Fill-Hole Poly-Hole Region-Hole Text-Hole)
Clearance "Schematic Clearance Constraint_21" [InNet('NetR19_1')] p98: gap=0.254 ignorepadtopadclearanceinfootprint=FALSE except(0: Arc-Hole Track-Hole SMDPad-Hole THPad-Hole Via-Hole Fill-Hole Poly-Hole Region-Hole Text-Hole)
Clearance "Schematic Clearance Constraint_19" [InNet('NetR26_2')] p99: gap=0.254 ignorepadtopadclearanceinfootprint=FALSE except(0: Arc-Hole Track-Hole SMDPad-Hole THPad-Hole Via-Hole Fill-Hole Poly-Hole Region-Hole Text-Hole)
Clearance "Schematic Clearance Constraint_18" [InNet('NetC29_1')] p100: gap=0.254 ignorepadtopadclearanceinfootprint=FALSE except(0: Arc-Hole Track-Hole SMDPad-Hole THPad-Hole Via-Hole Fill-Hole Poly-Hole Region-Hole Text-Hole)
Clearance "Schematic Clearance Constraint_17" [InNet('NetR32_2')] p101: gap=0.254 ignorepadtopadclearanceinfootprint=FALSE except(0: Arc-Hole Track-Hole SMDPad-Hole THPad-Hole Via-Hole Fill-Hole Poly-Hole Region-Hole Text-Hole)
Clearance "Schematic Clearance Constraint_16" [InNet('NetR52_1')] p102: gap=0.254 ignorepadtopadclearanceinfootprint=FALSE except(0: Arc-Hole Track-Hole SMDPad-Hole THPad-Hole Via-Hole Fill-Hole Poly-Hole Region-Hole Text-Hole)
Clearance "Schematic Clearance Constraint_15" [InNet('NetR53_1')] p103: gap=0.254 ignorepadtopadclearanceinfootprint=FALSE except(0: Arc-Hole Track-Hole SMDPad-Hole THPad-Hole Via-Hole Fill-Hole Poly-Hole Region-Hole Text-Hole)
Clearance "Schematic Clearance Constraint_14" [InNet('+3.3VSW')] p104: gap=0.254 ignorepadtopadclearanceinfootprint=FALSE except(0: Arc-Hole Track-Hole SMDPad-Hole THPad-Hole Via-Hole Fill-Hole Poly-Hole Region-Hole Text-Hole)
Clearance "Schematic Clearance Constraint_13" [InNet('NetR25_1')] p105: gap=0.254 ignorepadtopadclearanceinfootprint=FALSE except(0: Arc-Hole Track-Hole SMDPad-Hole THPad-Hole Via-Hole Fill-Hole Poly-Hole Region-Hole Text-Hole)
Clearance "Schematic Clearance Constraint_11" [InNet('NetD10_1')] p106: gap=0.254 ignorepadtopadclearanceinfootprint=FALSE except(0: Arc-Hole Track-Hole SMDPad-Hole THPad-Hole Via-Hole Fill-Hole Poly-Hole Region-Hole Text-Hole)
Clearance "Schematic Clearance Constraint_10" [InNet('NetU2_4')] p107: gap=0.254 ignorepadtopadclearanceinfootprint=FALSE except(0: Arc-Hole Track-Hole SMDPad-Hole THPad-Hole Via-Hole Fill-Hole Poly-Hole Region-Hole Text-Hole)
Clearance "Schematic Clearance Constraint_9" [InNet('NetU2_8')] p108: gap=0.254 ignorepadtopadclearanceinfootprint=FALSE except(0: Arc-Hole Track-Hole SMDPad-Hole THPad-Hole Via-Hole Fill-Hole Poly-Hole Region-Hole Text-Hole)
Clearance "Schematic Clearance Constraint_8" [InNet('NetU2_9')] p109: gap=0.254 ignorepadtopadclearanceinfootprint=FALSE except(0: Arc-Hole Track-Hole SMDPad-Hole THPad-Hole Via-Hole Fill-Hole Poly-Hole Region-Hole Text-Hole)
Clearance "Schematic Clearance Constraint_7" [InNet('NetU2_10')] p110: gap=0.254 ignorepadtopadclearanceinfootprint=FALSE except(0: Arc-Hole Track-Hole SMDPad-Hole THPad-Hole Via-Hole Fill-Hole Poly-Hole Region-Hole Text-Hole)
Clearance "Schematic Clearance Constraint_5" [InNet('NetU2_14')] p111: gap=0.254 ignorepadtopadclearanceinfootprint=FALSE except(0: Arc-Hole Track-Hole SMDPad-Hole THPad-Hole Via-Hole Fill-Hole Poly-Hole Region-Hole Text-Hole)
Clearance "Schematic Clearance Constraint_4" [InNet('+24V SWITCHED')] p112: gap=0.254 ignorepadtopadclearanceinfootprint=FALSE except(0: Arc-Hole Track-Hole SMDPad-Hole THPad-Hole Via-Hole Fill-Hole Poly-Hole Region-Hole Text-Hole)
Clearance "Schematic Clearance Constraint_3" [InNet('+24V SWITCHED')] p113: gap=0.254 ignorepadtopadclearanceinfootprint=FALSE except(0: Arc-Hole Track-Hole SMDPad-Hole THPad-Hole Via-Hole Fill-Hole Poly-Hole Region-Hole Text-Hole)
Clearance "Schematic Clearance Constraint_2" [InNet('+24VPRIM')] p114: gap=0.254 ignorepadtopadclearanceinfootprint=FALSE except(0: Arc-Hole Track-Hole SMDPad-Hole THPad-Hole Via-Hole Fill-Hole Poly-Hole Region-Hole Text-Hole)
Clearance "Schematic Clearance Constraint_1" [InNet('+12V SWITCHED')] p115: gap=0.254 ignorepadtopadclearanceinfootprint=FALSE except(0: Arc-Hole Track-Hole SMDPad-Hole THPad-Hole Via-Hole Fill-Hole Poly-Hole Region-Hole Text-Hole)
Clearance "Schematic Clearance Constraint" [InNet('+3.3VSEC')] p116: gap=0.254 ignorepadtopadclearanceinfootprint=FALSE except(0: Arc-Hole Track-Hole SMDPad-Hole THPad-Hole Via-Hole Fill-Hole Poly-Hole Region-Hole Text-Hole)
Clearance "Schematic Clearance Constraint_74" [InNet('NetR56_1')] p117: gap=0.508 ignorepadtopadclearanceinfootprint=FALSE except(0: Arc-Hole Track-Hole SMDPad-Hole THPad-Hole Via-Hole Fill-Hole Poly-Hole Region-Hole Text-Hole)
Clearance "Schematic Clearance Constraint_47" [InNet('NetR57_2')] p118: gap=0.254 ignorepadtopadclearanceinfootprint=FALSE except(0: Arc-Hole Track-Hole SMDPad-Hole THPad-Hole Via-Hole Fill-Hole Poly-Hole Region-Hole Text-Hole)
Clearance "Schematic Clearance Constraint_35" [InNet('NetD25_2')] p119: gap=0.762 ignorepadtopadclearanceinfootprint=FALSE except(0: Arc-Hole Track-Hole SMDPad-Hole THPad-Hole Via-Hole Fill-Hole Poly-Hole Region-Hole Text-Hole)
Clearance "Schematic Clearance Constraint_20" [InNet('NetQ15_1')] p120: gap=0.254 ignorepadtopadclearanceinfootprint=FALSE except(0: Arc-Hole Track-Hole SMDPad-Hole THPad-Hole Via-Hole Fill-Hole Poly-Hole Region-Hole Text-Hole)
Clearance "Schematic Clearance Constraint_6" [InNet('NetQ12_1')] p121: gap=0.254 ignorepadtopadclearanceinfootprint=FALSE except(0: Arc-Hole Track-Hole SMDPad-Hole THPad-Hole Via-Hole Fill-Hole Poly-Hole Region-Hole Text-Hole)
Clearance Clearance_Keepouts [((IsTrack Or IsArc) And Not InPoly) And IsFree and IsKeepOut vs ((IsTrack Or IsArc) And Not InPoly) And IsFree and IsKeepOut] p122: gap=0 ignorepadtopadclearanceinfootprint=FALSE
Clearance Clearance_BoardEdge_MountingHoles [OnCopper and InComponentClass('Mounting Holes') vs IsKeepOut] p123: gap=1.016 ignorepadtopadclearanceinfootprint=FALSE except(0: Arc-Hole Track-Hole SMDPad-Hole THPad-Hole Via-Hole Fill-Hole Poly-Hole Region-Hole Text-Hole)
Clearance Clearance_BoardEdge_Poly [OnCopper and InPoly vs IsKeepOut] p124: gap=0.635 ignorepadtopadclearanceinfootprint=FALSE except(0: Arc-Hole Track-Hole SMDPad-Hole THPad-Hole Via-Hole Fill-Hole Poly-Hole Region-Hole Text-Hole)
Clearance Clearance_BoardEdge [OnCopper and Not InComponentClass('Logo') and not InComponentClass('FiducialMark') and not InRegion(1000,500,4000,800) and Not IsKeepout vs IsKeepOut] p125: gap=1.905 ignorepadtopadclearanceinfootprint=FALSE except(0: Arc-Hole Track-Hole SMDPad-Hole THPad-Hole Via-Hole Fill-Hole Poly-Hole Region-Hole Text-Hole)
Clearance Clearance_Poly [InPolygon] p126: gap=0.635 ignorepadtopadclearanceinfootprint=FALSE except(0: Arc-Hole Track-Hole SMDPad-Hole THPad-Hole Via-Hole Fill-Hole Poly-Hole Region-Hole Text-Hole)
Clearance [All] p127: gap=0.2 ignorepadtopadclearanceinfootprint=FALSE except(0: Arc-Hole Track-Hole SMDPad-Hole THPad-Hole Via-Hole Fill-Hole Poly-Hole Region-Hole Text-Hole)
ComponentClearance ComponentClearance_MountingHoles_FiducialMarks [InComponentClass('Mounting Holes') vs InComponentClass('FiducialMark')] p1: gap=1.27 collisioncheckmode=3 verticalgap=0.254 showdistances=FALSE
ComponentClearance ComponentClearance_Shunt [InComponentClass('Header') vs InComponentClass('Shunt')] p2: gap=0 collisioncheckmode=3 verticalgap=0 showdistances=FALSE
ComponentClearance ComponentClearance_Logo [InComponentClass('Logo')] p3: gap=1.27 collisioncheckmode=3 verticalgap=0.254 showdistances=FALSE
ComponentClearance ComponentClearance_ScrewToNut [(HasFootprint('NY PMS 440 0025 PH')) vs (HasFootprint('Keystone_1902C'))] p4: gap=0.127 collisioncheckmode=3 verticalgap=0.254 showdistances=FALSE
ComponentClearance ComponentClearance_MountingHoles [InComponentClass('Mounting Holes')] p5: gap=6.35 collisioncheckmode=3 verticalgap=2540 showdistances=FALSE
ComponentClearance ComponentClearance_SmallPassives [HasFootprint('0201*') or HasFootprint('0402*') or HasFootprint('0508') or HasFootprint('0603*') or HasFootprint('0612') or HasFootprint('0805*') or HasFootprint('0815*') or HasFootprint('0830*') or HasFootprint('1206*') or HasFootprint('1210*') or HasFootprint('1808*') or HasFootprint('1812*') or HasFootprint('1825*') or HasFootprint('2010*') or HasFootprint('2220*') or HasFootprint('2225*') or HasFootprint('2512*') or HasFootprint('2728*') or HasFootprint('3518*') vs HasFootprint('0201*') or HasFootprint('0402*') or HasFootprint('0508') or HasFootprint('0603*') or HasFootprint('0612') or HasFootprint('0805*') or HasFootprint('0815*') or HasFootprint('0830*') or HasFootprint('1206*') or HasFootprint('1210*') or HasFootprint('1808*') or HasFootprint('1812*') or HasFootprint('1825*') or HasFootprint('2010*') or HasFootprint('2220*') or HasFootprint('2225*') or HasFootprint('2512*') or HasFootprint('2728*') or HasFootprint('3518*')] p6: gap=0.508 collisioncheckmode=3 verticalgap=0.254 showdistances=FALSE
ComponentClearance ComponentClearance_THtoSMT [IsThruComponent vs IsSMTComponent] p7: gap=0.5 collisioncheckmode=3 verticalgap=0.762 showdistances=FALSE
ComponentClearance ComponentClearance_THtoTH [IsThruComponent vs IsThruComponent] p8: gap=0.5 collisioncheckmode=3 verticalgap=0.762 showdistances=FALSE
ComponentClearance [All] p9: gap=0.5 collisioncheckmode=3 verticalgap=0.254 showdistances=FALSE
DiffPairsRouting [All] p1: maxlimit=2.54 minlimit=0.254 mostfreqgap=0.254 toplayer_minwidth=0.381 toplayer_maxwidth=0.381 toplayer_prefwidth=0.381 midlayer1_minwidth=0.381 midlayer1_maxwidth=0.381 midlayer1_prefwidth=0.381 midlayer2_minwidth=0.381 midlayer2_maxwidth=0.381 midlayer2_prefwidth=0.381 bottomlayer_minwidth=0.381 bottomlayer_maxwidth=0.381 bottomlayer_prefwidth=0.381 maxuncoupledlength=25.4
FabricationTestPointUsage TestPointUsage [All] p1: valid=2 allowmultiple=FALSE
FabricationTestpoint Testpoint [All] p1: side=3 testpointundercomponent=TRUE minsize=1.016 maxsize=2.54 preferedsize=1.524 minholesize=0 maxholesize=1.016 preferedholesize=0.813 testpointgrid=0.025 allowsidetop=TRUE allowsidebottom=TRUE usegrid=TRUE gridtolerance=0
FanoutControl Fanout_LCC [IsLCC] p1: bgadir=Out bgaviamode=Centered fanoutstyle=Auto fanoutdirection=Alternating viagrid=0.025 // Fanout_LCC (Default Rule)
FanoutControl Fanout_BGA [IsBGA] p2: bgadir=Out bgaviamode=Centered fanoutstyle=Auto fanoutdirection=Alternating viagrid=0.025 // Fanout_BGA (Default Rule)
FanoutControl Fanout_Default [All] p4: bgadir=Out bgaviamode=Centered fanoutstyle=Auto fanoutdirection=Alternating viagrid=0.025 // Fanout_Default (Default Rule)
FanoutControl Fanout_Small [(CompPinCount < 5)] p5: bgadir=Out bgaviamode=Centered fanoutstyle=Auto fanoutdirection=OutThenIn viagrid=0.025 // Fanout_Small (Default Rule)
HoleSize [All] p1: absolutevalues=TRUE maxlimit=6.375 minlimit=0.3 maxpercent=80.000 minpercent=20.000
MinimumAnnularRing MinimumAnnularRing_ThermalPadVias [IsVia and InAnyComponent] p1: minimumring=0.15
MinimumAnnularRing [All] p2: minimumring=0.229
MinimumSolderMaskSliver MinimumSolderMaskSliver_Logo [InComponentClass('Logo') vs InComponentClass('Logo')] p1: minsoldermaskwidth=0.018
MinimumSolderMaskSliver [All] p2: minsoldermaskwidth=0.1
PlaneConnect [All] p1: planeconnectstyle=Relief reliefexpansion=0.254 reliefentries=4 reliefconductorwidth=0.254 reliefairgap=0.254
PolygonConnect PolygonConnect_7 [All vs IsSMTPin] p1: connectstyle=Direct reliefconductorwidth=0.254 reliefentries=4 polygonreliefangle="90 Angle" airgapwidth=0.254
PolygonConnect PolygonConnect_8 [All vs IsVia] p2: connectstyle=Direct reliefconductorwidth=0.254 reliefentries=4 polygonreliefangle="90 Angle" airgapwidth=0.254
PolygonConnect PolygonConnect_6 [All vs IsNamedPolygon('Bottom Layer-No Net 8')] p3: connectstyle=Direct reliefconductorwidth=0.254 reliefentries=4 polygonreliefangle="90 Angle" airgapwidth=0.254
PolygonConnect PolygonConnect_5 [All vs IsNamedPolygon('Bottom Layer-No Net 7')] p4: connectstyle=Direct reliefconductorwidth=0.254 reliefentries=4 polygonreliefangle="90 Angle" airgapwidth=0.254
PolygonConnect PolygonConnect_4 [All vs IsNamedPolygon('Bottom Layer-No Net 6')] p5: connectstyle=Direct reliefconductorwidth=0.254 reliefentries=4 polygonreliefangle="90 Angle" airgapwidth=0.254
PolygonConnect PolygonConnect_3 [All vs IsNamedPolygon('Bottom Layer-No Net 5')] p6: connectstyle=Direct reliefconductorwidth=0.254 reliefentries=4 polygonreliefangle="90 Angle" airgapwidth=0.254
PolygonConnect PolygonConnect_2 [All vs IsNamedPolygon('Top Layer-No Net 2')] p7: connectstyle=Direct reliefconductorwidth=0.254 reliefentries=4 polygonreliefangle="90 Angle" airgapwidth=0.254
PolygonConnect [All vs IsNamedPolygon('Bottom Layer-No Net 4')] p8: connectstyle=Direct reliefconductorwidth=0.254 reliefentries=4 polygonreliefangle="90 Angle" airgapwidth=0.254
PolygonConnect PolygonConnect_1 [All] p9: connectstyle=Relief reliefconductorwidth=0.508 reliefentries=4 polygonreliefangle="90 Angle" airgapwidth=0.254
RoutingVias ThermalPadVias [IsVia and InAnyComponent] p1: holewidth=0.3 width=0.6 viastyle="Through Hole" minholewidth=0.3 minwidth=0.6 maxholewidth=0.5 maxwidth=0.7
RoutingVias [All] p2: holewidth=0.5 width=1 viastyle="Through Hole" minholewidth=0.3 minwidth=0.66 maxholewidth=1.016 maxwidth=1.651
SilkToBoardRegionClearance [Not ((IsComment or IsDesignator) And (Hide <> 'False')) and not InRegion(1000,500,4000,800)] p1:
SilkToSilkClearance SilkToSilkClearance_Pb-FreeLogo [(HasFootprint('Pb-Free_Overlay_Medium') OR HasFootprint('Pb-Free_Overlay_Small')) vs (HasFootprint('Pb-Free_Overlay_Medium') OR HasFootprint('Pb-Free_Overlay_Small'))] p1: silktosilkclearance=0
SilkToSilkClearance [All] p2: silktosilkclearance=0.102
SilkToSolderMaskClearance "Silk to Solder Mask Opening" [All] p1: minsilkscreentomaskgap=0.102 clearancetoexposedcopper=FALSE
SolderMaskExpansion [All] p1: expansion=0.05
Width [All] p1: maxlimit=2.54 minlimit=0.152 preferedwidth=0.254 checkconnectedcopper=TRUE
15 further rules are at their usual default settings.

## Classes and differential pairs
component class Header: J5
component class "PMP30183 Rev_A PFC Boost + Aux Schematic": C33 C34 C35 C36 C37 C38 C39 C40 C41 C42 C43 C44 C45 C46 C47 C48 C49 C50 C51 C52 C53 C54 C55 C56 C57 C58 C59 C60 D24 D25 D26 D28 D29 D30 D31 D32 D33 D34 D35 J4 L3 L4 L5 L7 L8 L10 L11 Q15 Q17 Q18 R55 R56 R57 R58 R59 R60 R61 R62 R63 R64 R65 R66 R69 R70 R71 R72 R73 R74 R75 R76 R77 R78 R79 R80 R81 R82 R83 R84 R85 R86 RT1 RV1 T2 TP1 TP11 TP12 TP17 TP19 TP23 TP24 TP26 TP28 U9 U10 U11 U12 U13 XF1 XF2
component class "PMP30183 Rev_A 2-Switch Forward Schematic": C1 C2 C3 C4 C5 C6 C7 C8 C9 C10 C11 C12 C13 C14 C15 C16 C17 C18 C19 C20 C21 C22 C23 C24 C25 C26 C27 C28 C29 C30 C31 C32 D1 D2 D3 D4 D5 D6 D7 D8 D9 D10 D11 D12 D13 D14 D15 D16 D17 D18 D19 D20 D21 D22 D23 D27 J1 J2 J3 J5 L1 L2 Q1 Q2 Q3 Q4 Q5 Q6 Q7 Q8 Q9 Q10 Q11 Q12 Q13 Q14 Q16 R1 R2 R3 R4 R5 R6 R7 R8 R9 R10 R11 R12 R13 R14 R15 R16 R17 R18 R19 R20 R21 R22 R23 R24 R25 R26 R27 R28 R29 R30 R31 R32 R33 R34 R35 R36 R37 R38 R39 R40 R41 R42 R43 R44 R45 R46 R47 R48 R49 R50 R51 R52 R53 R54 R67 R68 S1 T1 TP2 TP3 TP4 TP5 TP6 TP7 TP8 TP9 TP10 U1 U2 U3 U4 U5 U6 U7 U8

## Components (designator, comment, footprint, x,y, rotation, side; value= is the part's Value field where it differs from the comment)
C1 "C3216X7R2J103K" 1206 53.721,118.745 r90 bottom
C2 "C3225X7T2J104K160AC" 1210 56.769,118.745 r90 bottom
C3 "C3225X7T2J104K160AC" 1210 60.198,118.745 r90 bottom
C4 "C0805C102JBRACTU" 0805_HV 74.295,51.435 r270 bottom
C5 "C1608X7R1H104K" 0603#1 51.816,44.45 r90 bottom
C6 "GRM188R72E331KW07D" 0603#1 57.15,55.88 r90 bottom
C7 "GRM188R71E105KA12D" 0603#1 61.341,137.795 r90 bottom
C8 "C1608X7R1H104K" 0603#1 67.945,142.875 r0 bottom
C9 "C3216C0G2J221J" 1206 88.9,55.88 r90 bottom
C10 "EKZM500ELL102ML25S" CAPPR750W80D1600H3000 51.435,14.605 r270 top
C11 "EKZM500ELL102ML25S" CAPPR750W80D1600H3000 68.58,14.605 r270 top
C12 "EKZM500ELL102ML25S" CAPPR750W80D1600H3000 34.29,14.605 r270 top
C13 "C3225X7R1H106M250AC" 1210_280 17.78,18.415 r0 bottom
C14 "GRM55DR72E105KW01L" 2220_200 86.995,20.955 r90 bottom
C15 "VY2472M49Y5US63V7" VY2_1250x500x1650 49.53,76.2 r270 top
C16 "VY2472M49Y5US63V7" VY2_1250x500x1650 49.53,62.865 r270 top
C17 "C1812C104KARACTU" 1812 75.565,43.18 r90 bottom
C18 "C1608C0G1H101J" 0603#1 73.025,141.605 r90 bottom
C19 "C1608X7R1E105K080AB" 0603#1 69.85,31.75 r270 bottom
C20 "GRM188R71E105KA12D" 0603#1 33.655,22.225 r90 bottom
C21 "885012207103" 0805_HV 57.531,137.668 r90 bottom
C22 "C1608C0G1H101J" 0603#1 31.115,24.63 r180 bottom
C23 "C0603C334K4RACTU" 0603#2 46.429,136.612 r270 bottom
C24 "C1608C0G1H101J" 0603#1 48.895,133.985 r180 bottom
C25 "GRM188R71E105KA12D" 0603#1 59.563,137.795 r90 bottom
C26 "C1608X7R1H104K" 0603#1 29.845,27.17 r270 bottom
C27 "GRM188R71H102KA01D" 0603#1 55.88,146.431 r0 bottom
C28 "885012207103" 0805_HV 86.995,34.925 r270 bottom
C29 "C1608X8R1H102K" 0603#1 51.435,139.7 r180 bottom
C30 "GRM219R71H334KA88D" 0805_HV 22.86,25.4 r0 bottom
C31 "C2012X7R1E474K125AA" 0805_HV 34.925,32.885 r0 bottom
C32 "C1608X7R1E105K080AB" 0603#1 55.88,148.082 r0 bottom
C33 "GRM31BR72J102KW01L" 1206 19.05,130.81 r180 bottom
C34 "VY2472M49Y5US63V7" VY2_1250x500x1650 50.8,156.845 r270 top
C35 "450MXK150MEFCSN22X30" SMQ_2200X2500 53.975,107.315 r270 top
C36 "450MXK150MEFCSN22X30" SMQ_2200X2500 78.105,107.315 r270 top
C37 "ECQ-U2A474ML" CAPRR2250W80L2550T850H1750 43.18,163.83 r90 top
C38 "R46KN410000P1M" CAPRR2250W80L2550T850H1750 25.4,153.67 r180 top
C39 "C1608X7R1H102K" 0603#1 31.75,139.7 r90 bottom
C40 "C2012X5R1E475K125AB" 0805_HV 26.035,144.78 r180 bottom
C41 "C2012X7R1C225K" 0805_HV 26.035,147.32 r180 bottom
C42 "C1608X7R1C224K" 0603#1 31.75,143.51 r90 bottom
C43 "C1608C0G1H821J" 0603#1 19.685,137.16 r270 bottom
C44 "C1608X7R1H222K" 0603#1 21.59,137.16 r270 bottom
C45 "C1608X7R1H104K" 0603#3 31.75,135.89 r270 bottom
C46 "C3225X7T2J104K160AC" 1210 43.18,81.915 r0 bottom
C47 "EKZM160ELL471MHB5D" CAPPR3p5-8x16 31.115,50.8 r270 top
C48 "EKZM160ELL101ME11D" ML_500x500 23.495,50.8 r270 top
C49 "C1608X7R1C105K" 0603#1 13.335,46.355 r270 bottom
C50 "UPW1V470MED1TD" ZL_630x1100 19.685,76.835 r270 top
C51 "C2012X5R1E475K125AB" 0805_HV 27.305,46.99 r0 bottom
C52 "C2012X5R0J226M" 0805_HV 23.495,38.735 r270 bottom
C53 "UPW1H100MDD" ZLJ_500x1100 12.7,76.835 r270 top
C54 "C1608X7R1H104K" 0603#1 25.4,105.41 r0 bottom
C55 "C0603C334K4RACTU" 0603#1 31.242,98.679 r0 bottom
C56 "C1608X7R1C105K" 0603#1 20.701,101.6 r90 bottom
C57 "C1608X7R1H102K" 0603#1 25.4,103.759 r0 bottom
C58 "C1608C0G1H560J" 0603#1 21.59,58.42 r0 bottom
C59 "C1608X8R1H473K" 0603#1 22.479,60.706 r270 bottom
C60 "VY2472M49Y5US63V7" VY2_1250x500x1650 50.8,170.18 r270 top
D1 "MURA160T3G" SMA 69.723,146.685 r180 bottom
D2 "SMBJ150A-13-F" SMB 70.485,52.07 r270 bottom
D3 "MBRS3200T3G" SMB 64.135,55.88 r180 bottom
D4 "MURS160T3G" SMB 66.04,118.745 r0 bottom
D5 "MBR20200CTG" TO-220AB 63.5,50.8 r180 top
D6 "MURA160T3G" SMA 78.105,135.89 r270 bottom
D7 "MBR20200CTG" TO-220AB 82.55,50.8 r180 top
D8 "MURS160T3G" SMB 80.01,118.745 r180 bottom
D9 "MBRS3200T3G" SMB 80.01,43.18 r90 bottom
D10 "BAS21-7-F" SOT-23 73.66,137.66 r0 bottom
D11 "SMBJ150A-13-F" SMB 71.12,43.18 r90 bottom
D12 "BZT52C5V1T-7" SOD-523 67.945,31.75 r270 bottom
D13 "SMAJ58A" SMA 74.295,36.195 r180 bottom
D14 "BAT42WS-7-F" sod-323 76.2,31.115 r270 bottom
D15 "ES1D-13-F" SMA 81.915,24.765 r90 bottom
D16 "MMSZ5243BS-7-F" sod-323 38.735,19.05 r180 bottom
D17 "SMAJ58A" SMA 67.31,36.195 r180 bottom
D18 "BZT52C6V8T-7" SOD-523 51.435,143.51 r180 bottom
D19 "BAS21-7-F" SOT-23 26.67,25.9 r270 bottom
D20 "BAS21-7-F" SOT-23 20.32,28.575 r90 bottom
D21 "LTST-C170KSKT" LED_LTST-C170 11.43,33.02 r0 top
D22 "LTST-C170KGKT" LTST-C170KGKT_Green 11.43,30.57 r0 top
D23 "LTST-C170KGKT" LTST-C170KGKT_Green 11.43,27.94 r0 top
D24 "S3JB-13-F" SMB 45.72,116.205 r180 bottom
D25 "LXA06T600" TO-220-F2 51.637,125.641 r0 top
D26 "GBU806" GBU 16.839,126.244 r180 top
D27 "BAS21-7-F" SOT-23 7.62,28.575 r90 bottom
D28 "BAS21-7-F" SOT-23 20.955,141.605 r90 bottom
D29 "MMSZ5243BS-7-F" sod-323 15.621,96.534 r180 bottom
D30 "STPS1150A" SMA 34.29,56.515 r0 bottom
D31 "SMAJ120A" SMA 41.91,88.265 r270 bottom
D32 "US1K-13-F" SMA 32.385,89.535 r180 bottom
D33 "RF071M2STR" SOD-123 19.177,80.772 r0 bottom
D34 "BAS21-7-F" SOT-23 13.462,80.645 r180 bottom
D35 "MMSZ4711-T1G" SOD-123 16.51,76.835 r270 bottom
J1 "923345-01-C" 3M_923345-01-C 66.04,113.665 r90 top
J2 "1732720" Phoenix_1732720 17.675,19.815 r0 top
J3 "39357-0003" Molex_39357-0003 11.43,56.515 r270 top
J4 "39357-0003" Molex_39357-0003 11.43,45.085 r270 top
J5 "0022284023" Molex_0022284023 18.415,37.465 r0 top
L1 "750315814r01" 750315814 44.45,39.37 r270 top
L2 "74477030" WE-PD_1280 84.095,20.32 r0 top
L3 "7447016" WE-FI_1900x1050 32.385,168.275 r270 top
L4 "750316373" 750316373 23.495,100.965 r270 top
L5 "744824433" IND_WE-CMB_L 63.5,163.83 r270 top
L8 "7447016" WE-FI_1900x1050 20.32,168.275 r270 top
L10 "744773047" WE-PD2-S 27.305,53.34 r180 bottom
L11 "74408943220" WE-SPC_4838 27.94,38.735 r180 bottom
Q1 "IPP50R199CP" TO-220AB 82.753,125.727 r0 top
Q2 "IPP50R199CP" TO-220AB 66.875,125.705 r0 top
Q3 "STN1NK60Z" SOT-223 84.455,143.51 r270 bottom
Q4 "2N7002E-T1-E3" SOT-23 76.2,141.605 r0 bottom
Q5 "ZVP4424GTA" SOT-223 73.025,24.13 r270 bottom
Q6 "MMBT3904" SOT-23 36.83,22.225 r90 bottom
Q7 "MMBT3906" SOT-23 52.07,146.05 r0 bottom
Q8 "MMBT3904" SOT-23 46.99,140.97 r180 bottom
Q9 "BSS138" SOT-23 34.925,27.17 r270 bottom
Q10 "BSS138" SOT-23 16.51,28.575 r90 bottom
Q11 "MMBT3906" SOT-23 26.67,29.71 r270 bottom
Q12 "MMBT2907A" SOT-23 13.97,93.345 r90 bottom
Q13 "BSS138" SOT-23 20.32,33.02 r90 bottom
Q14 "BSS138" SOT-23 16.51,33.02 r90 bottom
Q15 "IPP50R140CP" TO-220AB 36.195,125.73 r0 top
Q16 "BSS138" SOT-23 11.43,26.67 r270 bottom
Q17 "PZT2222A" SOT-223 14.605,103.9 r90 bottom
Q18 "SPD02N80C3ATMA1" DPAK 24.765,91.44 r270 bottom
R1 "CRCW08052R21FKEA" 0805_HV 64.008,143.129 r180 bottom
R2 "RC1206FR-072R2L" 1206 63.5,146.685 r180 bottom
R3 "CRCW0603100RFKEA" 0603#1 50.165,44.45 r90 bottom
R4 "CRCW060329K4FKEA" 0603#1 53.848,47.371 r0 bottom
R5 "CRCW251268R1FKEG" 2512 69.215,64.77 r180 bottom
R6 "CRCW251268R1FKEG" 2512 60.96,64.77 r180 bottom
R7 "CRCW06034R75FKEA" 0603#1 76.835,126.365 r270 bottom
R8 "CRCW060310K0FKEA" 0603#1 83.185,122.555 r0 bottom
R9 "CRCW251268R1FKEG" 2512 86.36,64.77 r0 bottom
R10 "CRCW06034R75FKEA" 0603#1 64.135,130.175 r270 bottom
R11 "CRCW06031K00FKEA" 0603#1 74.93,144.145 r180 bottom
R12 "CRCW251268R1FKEG" 2512 78.105,64.77 r0 bottom
R13 "CRCW060310K0FKEA" 0603#1 68.58,129.54 r0 bottom
R14 "2-2176057-1" 2512 59.69,127 r90 bottom
R15 "CRCW06034K75FKEA" 0603#1 73.66,135.12 r180 bottom
R16 "CRCW12064K75FKEA" 1206 80.01,35.56 r90 bottom
R17 "CRCW06031K00FKEA" 0603#1 79.375,31.75 r180 bottom
R18 "CRCW06031K00FKEA" 0603#2 56.515,133.985 r0 bottom
R19 "CRCW06031K00FKEA" 0603#1 6.858,62.23 r0 bottom
R20 "CRCW1206698KFKEA" 1206 40.005,135.89 r270 bottom
R21 "CRCW060323K7FKEA" 0603#1 40.005,22.225 r270 bottom
R22 "CRCW06033K32FKEA" 0603#1 48.895,146.05 r90 bottom
R23 "CRCW06032K21FKEA" 0603#1 6.858,64.135 r0 bottom
R24 "CRCW201068K1FKEF" 2010 83.82,34.925 r270 bottom
R25 "CRCW1206715KFKEA" 1206 40.005,140.97 r270 bottom
R26 "CRCW060316K5FKEA" 0603#2 47.927,136.617 r90 bottom
R27 "CRCW060368K1FKEA" 0603#1 32.385,27.17 r90 bottom
R28 "CRCW251233R2FKEG" 2512 78.74,13.97 r0 bottom
R29 "CRCW1206715KFKEA" 1206 40.005,146.05 r270 bottom
R30 "CRCW06031M21FKEA" 0603#1 55.88,144.78 r180 bottom
R31 "CRCW060347K5FKEA" 0603#1 54.61,141.605 r90 bottom
R32 "CRCW060349R9FKEA" 0603#1 26.035,22.065 r270 bottom
R33 "CRCW060368K1FKEA" 0603#1 52.705,133.985 r180 bottom
R34 "CRCW060368K1FKEA" 0603#1 27.94,22.065 r270 bottom
R35 "CRCW0603221KFKEA" 0603#1 47.625,143.51 r180 bottom
R36 "CRCW060310K0FKEA" 0603#1 27.94,18.89 r90 bottom
R37 "RC0603FR-0715KL" 0603#1 22.86,23.495 r0 bottom
R38 "CRCW06036K81FKEA" 0603#1 58.547,145.669 r270 bottom
R39 "CRCW060347K5FKEA" 0603#1 51.435,141.351 r0 bottom
R40 "CRCW0603100KFKEA" 0603#1 23.495,28.44 r270 bottom
R41 "CRCW060310K0FKEA" 0603#1 26.67,32.885 r180 bottom
R42 "CRCW0603100KFKEA" 0603#1 23.495,33.52 r270 bottom
R43 "CRCW060310K0FKEA" 0603#1 7.62,25.4 r0 bottom
R44 "RC0603FR-0747K5L" 0603#1 29.845,31.615 r90 bottom
R45 "CRCW0603100RFKEA" 0603#1 12.7,33.655 r0 bottom
R46 "CRCW0603100RFKEA" 0603#1 8.89,32.385 r270 bottom
R47 "CRCW0603100KFKEA" 0603#1 15.24,25.4 r0 bottom
R48 "RC0603FR-0716K2L" 0603#1 34.925,30.345 r180 bottom
R49 "RC0603FR-07475KL" 0603#1 31.75,31.615 r90 bottom
R50 "CRCW0603100KFKEA" 0603#1 13.97,90.17 r180 bottom
R51 "CRCW060310K0FKEA" 0603#1 12.7,97.155 r270 bottom
R52 "CRCW060333K2FKEA" 0603#1 17.145,93.345 r90 bottom
R53 "CRCW06031K00FKEA" 0603#1 17.78,63.5 r270 bottom
R54 "CRCW0603100RFKEA" 0603#1 12.7,31.75 r180 bottom
R55 "RC1206FR-07475KL" 1206 61.595,160.02 r270 bottom
R56 "CRCW12061M00FKEA" 1206 36.83,135.89 r270 bottom
R57 "CRCW08052R21FKEA" 0805_HV 32.385,130.175 r180 bottom
R58 "CRCW060310K0FKEA" 0603#1 36.195,129.54 r180 bottom
R59 "CRCW12061M00FKEA" 1206 36.83,140.97 r270 bottom
R60 "RC1206FR-07475KL" 1206 61.595,167.005 r270 bottom
R61 "CSRN2512FK75L0" 2512 16.51,142.24 r270 bottom
R62 "CRCW12061M00FKEA" 1206 36.83,146.05 r270 bottom
R63 "CSRN2512FK75L0" 2512 12.065,142.24 r270 bottom
R64 "CRCW0603221RFKEA" 0603#1 20.955,145.415 r90 bottom
R65 "CRCW060333K2FKEA" 0603#1 29.845,143.51 r270 bottom
R66 "CRCW060338K3FKEA" 0603#1 33.655,139.7 r270 bottom
R67 "CRCW060310K0FKEA" 0603#1 11.43,29.845 r0 bottom
R68 "0 Ohm" 0603#1 43.815,140.97 r270 bottom
R69 "CRCW060317K8FKEA" 0603#1 26.035,142.24 r180 bottom
R70 "CRCW060310K0FKEA" 0603#1 15.621,98.312 r0 bottom
R71 "CRCW1206332KFKEA" 1206 40.64,105.41 r0 bottom
R72 "CRCW080551R0JNEA" 0805_HV 38.1,89.535 r0 bottom
R73 "CRCW1206332KFKEA" 1206 35.56,105.41 r0 bottom
R74 "CRCW060310R0FKEA" 0603#1 27.305,56.769 r180 bottom
R75 "CRCW1206332KFKEA" 1206 30.621,105.385 r0 bottom
R76 "CRCW060322R1FKEA" 0603#1 9.525,80.772 r180 bottom
R77 "CRCW060349R9FKEA" 0603#1 24.13,64.135 r270 bottom
R78 "CRCW060361K9FKEA" 0603#1 30.48,43.18 r270 bottom
R79 "CRCW0603392RFKEA" 0603#1 26.67,97.155 r0 bottom
R80 "CRCW060320K0FKEA" 0603#1 30.48,46.355 r270 bottom
R81 "CRCW12061R82FKEA" 1206 29.845,95.25 r270 bottom
R82 "CRCW060327K4FKEA" 0603#1 31.242,100.33 r180 bottom
R83 "CRCW060386K6FKEA" 0603#1 17.145,59.69 r270 bottom
R84 "CRCW06032K21FKEA" 0603#1 21.59,63.5 r180 bottom
R85 "CRCW0603100KFKEA" 0603#1 20.574,60.706 r90 bottom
